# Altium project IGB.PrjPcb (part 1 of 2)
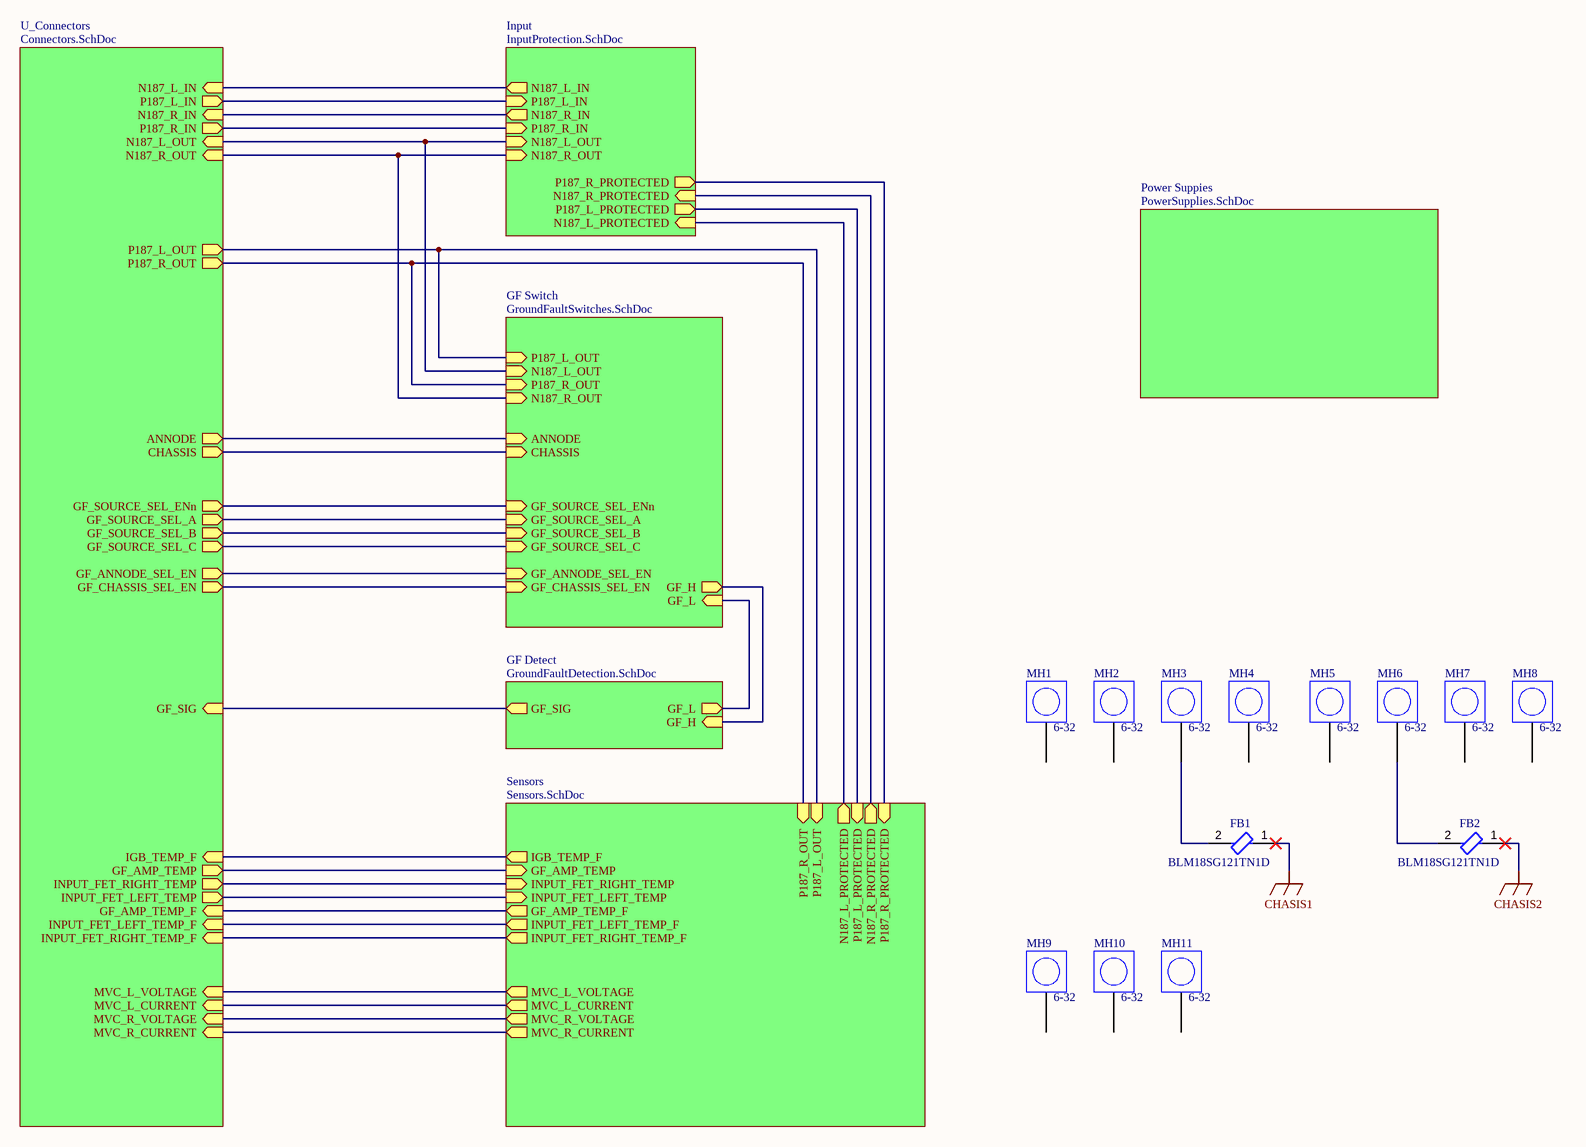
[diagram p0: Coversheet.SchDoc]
Gbl_Cage: 98514; Gbl_CheckedBy: B. SALMI; Gbl_DOC_NO_ASSY_DWG: 91263; Gbl_DOC_NO_BOM: 91261; Gbl_DOC_NO_FAB_DWG: 91262; Gbl_DOC_NO_SCH_DWG: 91255; Gbl_DrawnBy: K.ZACK; Gbl_DSN_APP_DATE: 8/21/2023; Gbl_ENG_APP_DATE: 8/21/2023; Gbl_Engineer: K. ZACK; Gbl_PCB_DWG_NO: 91256; Gbl_Project: MARS2 LVPS; Gbl_Revision: A
7 sheets, 229 parts. Net scope: hierarchical (ports join the sheet entries above them; power ports are global).
Board file: IGB.PcbDoc
Sheets:
  Coversheet.SchDoc
    U_Connectors = Connectors.SchDoc
    GF Detect = GroundFaultDetection.SchDoc
    GF Switch = GroundFaultSwitches.SchDoc
    Input = InputProtection.SchDoc
    Sensors = Sensors.SchDoc
    Power Suppies = PowerSupplies.SchDoc

## Sheet Coversheet.SchDoc: MARS2 LVPS - IGB - Main
size 431 x 279 mm; Organization: ORGANIZATION; Address1: APPLIED PHYSICS LAB; Address2: UNIVERSITY OF WASHINGTON; Address3: 1013 NE 40TH STREET; Address4: SEATTLE, WA 98105; DocumentNumber: 1; Revision: -; SheetNumber: 1; SheetTotal: 7; ENG_APP_DATE: --/--/--; DSN_APP_DATE: --/--/--; CHK_APP_DATE: --/--/--

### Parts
FB1  BLM18SG121TN1D  [FP-BLM18-0_15-t0_5-d1_2-IPC_B]
FB2  BLM18SG121TN1D  [FP-BLM18-0_15-t0_5-d1_2-IPC_B]
MH1  Fastener Size: 6-32  [MH-M3-Footprint-1 - Oversized MARS2]  (hidden comment: MH-MARS2-6-32)  (no BOM)
MH2  Fastener Size: 6-32  [MH-M3-Footprint-1 - Oversized MARS2]  (hidden comment: MH-MARS2-6-32)  (no BOM)
MH3  Fastener Size: 6-32  [MH-M3-Footprint-1 - Oversized MARS2]  (hidden comment: MH-MARS2-6-32)  (no BOM)
MH4  Fastener Size: 6-32  [MH-M3-Footprint-1 - Oversized MARS2]  (hidden comment: MH-MARS2-6-32)  (no BOM)
MH5  Fastener Size: 6-32  [MH-M3-Footprint-1 - Oversized MARS2]  (hidden comment: MH-MARS2-6-32)  (no BOM)
MH6  Fastener Size: 6-32  [MH-M3-Footprint-1 - Oversized MARS2]  (hidden comment: MH-MARS2-6-32)  (no BOM)
MH7  Fastener Size: 6-32  [MH-M3-Footprint-1 - Oversized MARS2]  (hidden comment: MH-MARS2-6-32)  (no BOM)
MH8  Fastener Size: 6-32  [MH-M3-Footprint-1 - Oversized MARS2]  (hidden comment: MH-MARS2-6-32)  (no BOM)
MH9  Fastener Size: 6-32  [MH-M3-Footprint-1 - Oversized MARS2]  (hidden comment: MH-MARS2-6-32)  (no BOM)
MH10  Fastener Size: 6-32  [MH-M3-Footprint-1 - Oversized MARS2]  (hidden comment: MH-MARS2-6-32)  (no BOM)
MH11  Fastener Size: 6-32  [MH-M3-Footprint-1 - Oversized MARS2]  (hidden comment: MH-MARS2-6-32)  (no BOM)

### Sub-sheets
GF Detect = GroundFaultDetection.SchDoc: GF_H (in), GF_SIG (out), GF_L (out)
GF Switch = GroundFaultSwitches.SchDoc: GF_SOURCE_SEL_A (in), GF_SOURCE_SEL_B (in), GF_SOURCE_SEL_ENn (in), N187_R_OUT (in), P187_R_OUT (in), GF_CHASSIS_SEL_EN (in), GF_H (out), P187_L_OUT (in), GF_SOURCE_SEL_C (in), GF_ANNODE_SEL_EN (in), GF_L (in), N187_L_OUT (in), ANNODE (in), CHASSIS (in)
Input = InputProtection.SchDoc: P187_L_IN (in), P187_R_IN (in), P187_R_PROTECTED (out), P187_L_PROTECTED (out), N187_R_IN (out), N187_R_OUT (in), N187_L_IN (out), N187_L_OUT (in), N187_R_PROTECTED (in), N187_L_PROTECTED (in)
Power Suppies = PowerSupplies.SchDoc: no entries
Sensors = Sensors.SchDoc: IGB_TEMP_F (out), GF_AMP_TEMP (in), INPUT_FET_RIGHT_TEMP (in), INPUT_FET_LEFT_TEMP (in), GF_AMP_TEMP_F (out), INPUT_FET_LEFT_TEMP_F (out), INPUT_FET_RIGHT_TEMP_F (out), P187_R_PROTECTED (in), P187_L_PROTECTED (in), MVC_L_CURRENT (out), MVC_L_VOLTAGE (out), MVC_R_CURRENT (out), MVC_R_VOLTAGE (out), N187_R_PROTECTED (out), N187_L_PROTECTED (out), P187_R_OUT (in), P187_L_OUT (in)
U_Connectors = Connectors.SchDoc: P187_R_IN (out), P187_L_IN (out), ANNODE (out), GF_SOURCE_SEL_ENn (out), GF_SIG (in), GF_SOURCE_SEL_A (out), GF_CHASSIS_SEL_EN (out), GF_ANNODE_SEL_EN (out), GF_SOURCE_SEL_C (out), GF_SOURCE_SEL_B (out), INPUT_FET_LEFT_TEMP_F (in), IGB_TEMP_F (in), GF_AMP_TEMP (out), INPUT_FET_RIGHT_TEMP (out), INPUT_FET_RIGHT_TEMP_F (in), INPUT_FET_LEFT_TEMP (out), GF_AMP_TEMP_F (in), CHASSIS (out), MVC_R_CURRENT (in), MVC_L_CURRENT (in), MVC_R_VOLTAGE (in), MVC_L_VOLTAGE (in), N187_R_IN (in), N187_L_IN (in), P187_R_OUT (out), N187_R_OUT (in), P187_L_OUT (out), N187_L_OUT (in)

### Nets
CHASIS1: FB1.1
CHASIS2: FB2.1
GF_SOURCE_SEL_ENn: sheet U_Connectors/GF_SOURCE_SEL_ENn, sheet GF Switch/GF_SOURCE_SEL_ENn
L_INPUT_COMMON: sheet Input/N187_L_PROTECTED, sheet Sensors/N187_L_PROTECTED
N187_L_OUT: sheet U_Connectors/N187_L_IN, sheet U_Connectors/N187_L_OUT, sheet GF Switch/N187_L_OUT, sheet Input/N187_L_IN, sheet Input/N187_L_OUT
N187_R_OUT: sheet U_Connectors/N187_R_IN, sheet U_Connectors/N187_R_OUT, sheet GF Switch/N187_R_OUT, sheet Input/N187_R_IN, sheet Input/N187_R_OUT
P187_L_OUT: sheet U_Connectors/P187_L_OUT, sheet GF Switch/P187_L_OUT, sheet Sensors/P187_L_OUT
P187_R_OUT: sheet U_Connectors/P187_R_OUT, sheet GF Switch/P187_R_OUT, sheet Sensors/P187_R_OUT
R_INPUT_COMMON: sheet Input/N187_R_PROTECTED, sheet Sensors/N187_R_PROTECTED
NetC21_2: sheet U_Connectors/MVC_R_CURRENT, sheet Sensors/MVC_R_CURRENT
NetC22_2: sheet U_Connectors/GF_AMP_TEMP_F, sheet Sensors/GF_AMP_TEMP_F
NetC23_2: sheet U_Connectors/INPUT_FET_LEFT_TEMP_F, sheet Sensors/INPUT_FET_LEFT_TEMP_F
NetC24_2: sheet U_Connectors/INPUT_FET_RIGHT_TEMP_F, sheet Sensors/INPUT_FET_RIGHT_TEMP_F
NetC25_2: sheet U_Connectors/MVC_R_VOLTAGE, sheet Sensors/MVC_R_VOLTAGE
NetC26_2: sheet U_Connectors/IGB_TEMP_F, sheet Sensors/IGB_TEMP_F
NetC29_2: sheet U_Connectors/MVC_L_CURRENT, sheet Sensors/MVC_L_CURRENT
NetC30_2: sheet U_Connectors/MVC_L_VOLTAGE, sheet Sensors/MVC_L_VOLTAGE
NetFB1_2: FB1.2 MH3.1
NetFB2_2: FB2.2 MH6.1
NetJ1_A: sheet U_Connectors/P187_R_IN, sheet Input/P187_R_IN
NetJ2_A: sheet U_Connectors/P187_L_IN, sheet Input/P187_L_IN
NetJ3_1: sheet U_Connectors/ANNODE, sheet GF Switch/ANNODE
NetJ3_2: sheet U_Connectors/CHASSIS, sheet GF Switch/CHASSIS
NetJ9_1: sheet U_Connectors/GF_SOURCE_SEL_A, sheet GF Switch/GF_SOURCE_SEL_A
NetJ9_3: sheet U_Connectors/GF_SOURCE_SEL_B, sheet GF Switch/GF_SOURCE_SEL_B
NetJ9_5: sheet U_Connectors/GF_SOURCE_SEL_C, sheet GF Switch/GF_SOURCE_SEL_C
NetJ9_9: sheet U_Connectors/GF_ANNODE_SEL_EN, sheet GF Switch/GF_ANNODE_SEL_EN
NetJ9_11: sheet U_Connectors/GF_CHASSIS_SEL_EN, sheet GF Switch/GF_CHASSIS_SEL_EN
NetJ9_47: sheet U_Connectors/GF_SIG, sheet GF Detect/GF_SIG
NetJ10_1: sheet U_Connectors/GF_AMP_TEMP, sheet Sensors/GF_AMP_TEMP
NetJ10_2: sheet U_Connectors/INPUT_FET_RIGHT_TEMP, sheet Sensors/INPUT_FET_RIGHT_TEMP
NetJ10_3: sheet U_Connectors/INPUT_FET_LEFT_TEMP, sheet Sensors/INPUT_FET_LEFT_TEMP
NetJ17_1: sheet Input/P187_R_PROTECTED, sheet Sensors/P187_R_PROTECTED
NetJ20_1: sheet Input/P187_L_PROTECTED, sheet Sensors/P187_L_PROTECTED
NetJ21_1: sheet GF Detect/GF_H, sheet GF Switch/GF_H
NetJ22_1: sheet GF Detect/GF_L, sheet GF Switch/GF_L

Not connected (* = marked no-connect by the designer): MH1 1; MH2 1; MH4 1; MH5 1; MH7 1; MH8 1; MH9 1; MH10 1; MH11 1

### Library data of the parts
FB1 FB2 = CMP-00000-1: Ferrite Beads Multi-Layer 120Ohm 25% 100MHz 3A 0.025Ohm DCR 0603 T/R; DC Resistance (DCR): 25mR; Number of Circuits: 1; Shielding: Unshielded; Material: Steel,Ferrite; Impedance: 120R
MH1-MH11 = CMP-00028-00015-1: MARS2 Project 6-32 Mounting Hole Plated .; Plated: Yes

## Sheet Connectors.SchDoc: MARS2 LVPS - IGB - Connectors
size 431 x 279 mm; Organization: ORGANIZATION; Address1: APPLIED PHYSICS LAB; Address2: UNIVERSITY OF WASHINGTON; Address3: 1013 NE 40TH STREET; Address4: SEATTLE, WA 98105; DocumentNumber: 2; Revision: -; SheetNumber: 2; SheetTotal: 7; ENG_APP_DATE: --/--/--; DSN_APP_DATE: --/--/--; CHK_APP_DATE: --/--/--
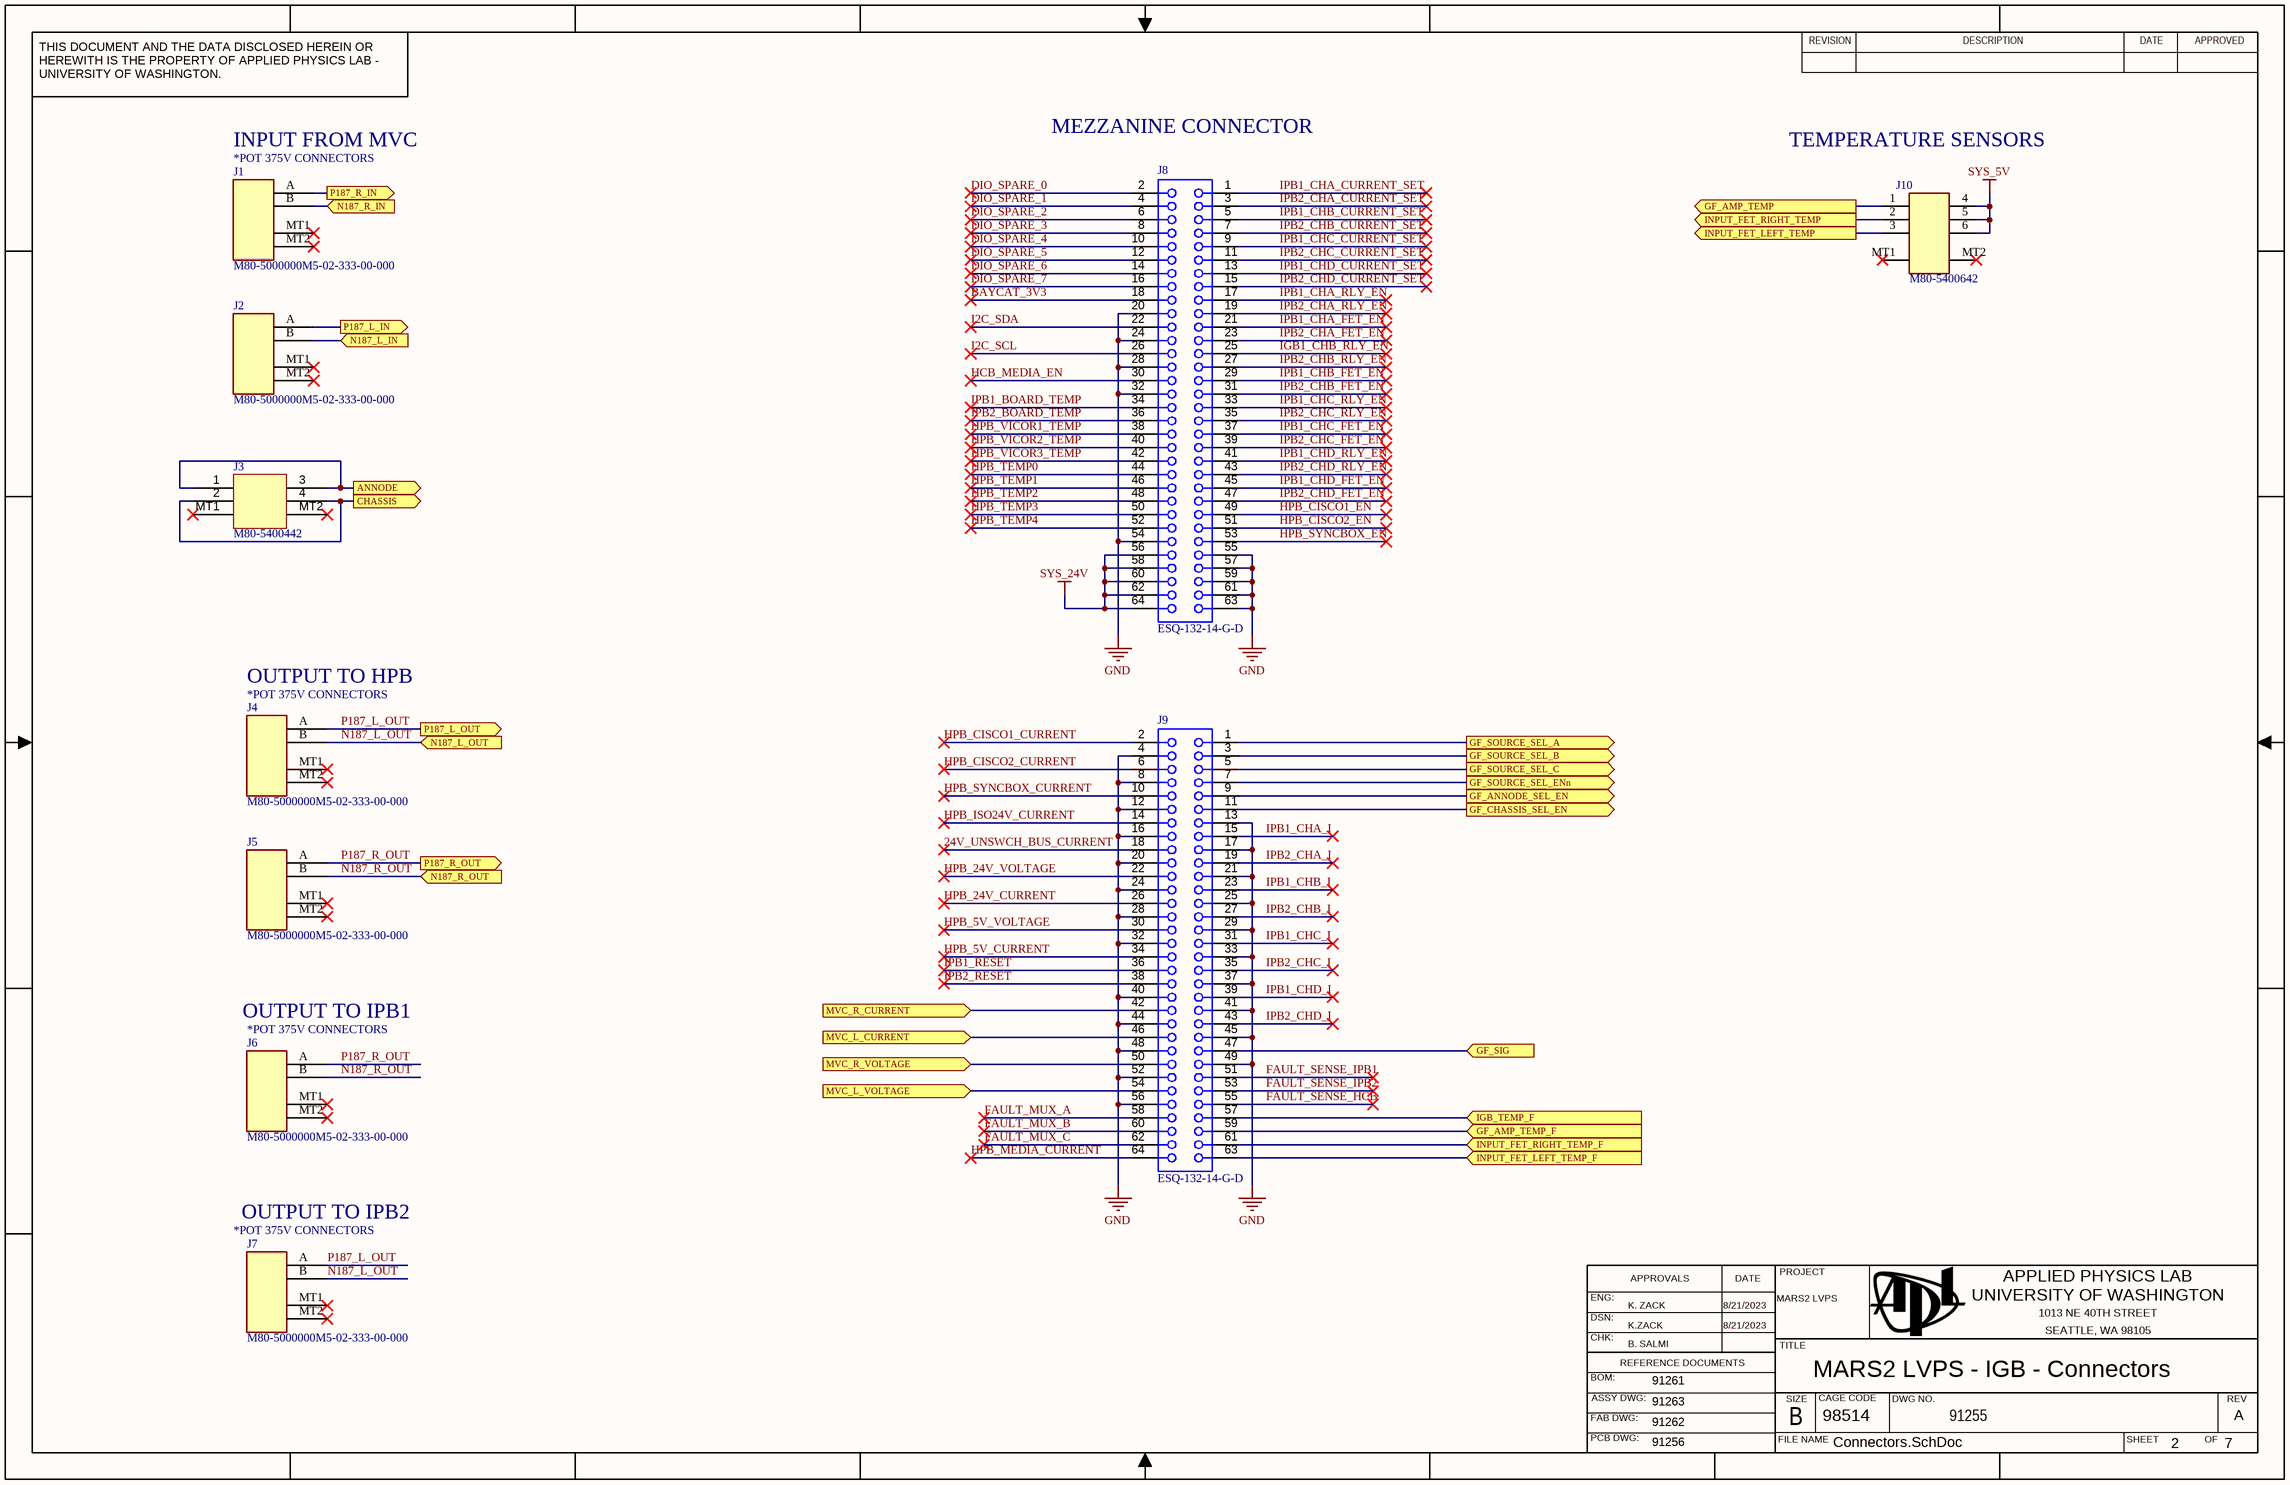
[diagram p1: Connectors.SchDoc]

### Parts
J1  M80-5000000M5-02-333-00-000  [FP-M80-5000000M5-02-333-0-MFG]
J2  M80-5000000M5-02-333-00-000  [FP-M80-5000000M5-02-333-0-MFG]
J3  M80-5400442  [M80-5400442-Footprint-1]
J4  M80-5000000M5-02-333-00-000  [FP-M80-5000000M5-02-333-0-MFG]
J5  M80-5000000M5-02-333-00-000  [FP-M80-5000000M5-02-333-0-MFG]
J6  M80-5000000M5-02-333-00-000  [FP-M80-5000000M5-02-333-0-MFG]
J7  M80-5000000M5-02-333-00-000  [FP-M80-5000000M5-02-333-0-MFG]
J8  ESQ-132-14-G-D  [SMTC-ESQ-132-14-X-D]
J9  ESQ-132-14-G-D  [SMTC-ESQ-132-14-X-D]
J10  M80-5400642  [FP-M80-5400642-MFG]

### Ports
ANNODE (out), CHASSIS (out), GF_AMP_TEMP (out), GF_AMP_TEMP_F (in), GF_ANNODE_SEL_EN (out), GF_CHASSIS_SEL_EN (out), GF_SIG (in), GF_SOURCE_SEL_A (out), GF_SOURCE_SEL_B (out), GF_SOURCE_SEL_C (out), GF_SOURCE_SEL_ENn (out), IGB_TEMP_F (in), INPUT_FET_LEFT_TEMP (out), INPUT_FET_LEFT_TEMP_F (in), INPUT_FET_RIGHT_TEMP (out), INPUT_FET_RIGHT_TEMP_F (in), MVC_L_CURRENT (in), MVC_L_VOLTAGE (in), MVC_R_CURRENT (in), MVC_R_VOLTAGE (in), N187_L_IN (in), N187_L_OUT (in), N187_R_IN (in), N187_R_OUT (in), P187_L_IN (out), P187_L_OUT (out), P187_R_IN (out), P187_R_OUT (out)

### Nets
GND: J8.20 J8.24 J8.28 J8.32 J8.54 J8.55 J8.57 J8.59 J8.61 J8.63 J9.4 J9.8 J9.12 J9.13 J9.16 J9.17 J9.20 J9.21 J9.24 J9.25 J9.28 J9.29 J9.32 J9.33 J9.37 J9.40 J9.41 J9.44 J9.45 J9.48 J9.49 J9.52 J9.56
SYS_5V: J10.4 J10.5 J10.6
SYS_24V: J8.56 J8.58 J8.60 J8.62 J8.64
24V_UNSWCH_BUS_CURRENT: J9.18
BAYCAT_3V3: J8.18
DIO_SPARE_0: J8.2
DIO_SPARE_1: J8.4
DIO_SPARE_2: J8.6
DIO_SPARE_3: J8.8
DIO_SPARE_4: J8.10
DIO_SPARE_5: J8.12
DIO_SPARE_6: J8.14
DIO_SPARE_7: J8.16
FAULT_MUX_A: J9.58
FAULT_MUX_B: J9.60
FAULT_MUX_C: J9.62
FAULT_SENSE_HCB: J9.55
FAULT_SENSE_IPB1: J9.51
FAULT_SENSE_IPB2: J9.53
GF_SOURCE_SEL_ENn: J9.7 ; port GF_SOURCE_SEL_ENn
HCB_MEDIA_EN: J8.30
HPB_5V_CURRENT: J9.34
HPB_5V_VOLTAGE: J9.30
HPB_24V_CURRENT: J9.26
HPB_24V_VOLTAGE: J9.22
HPB_CISCO1_CURRENT: J9.2
HPB_CISCO1_EN: J8.49
HPB_CISCO2_CURRENT: J9.6
HPB_CISCO2_EN: J8.51
HPB_ISO24V_CURRENT: J9.14
HPB_MEDIA_CURRENT: J9.64
HPB_SYNCBOX_CURRENT: J9.10
HPB_SYNCBOX_EN: J8.53
HPB_TEMP0: J8.44
HPB_TEMP1: J8.46
HPB_TEMP2: J8.48
HPB_TEMP3: J8.50
HPB_TEMP4: J8.52
HPB_VICOR1_TEMP: J8.38
HPB_VICOR2_TEMP: J8.40
HPB_VICOR3_TEMP: J8.42
I2C_SCL: J8.26
I2C_SDA: J8.22
IGB1_CHB_RLY_EN: J8.25
IPB1_BOARD_TEMP: J8.34
IPB1_CHA_CURRENT_SET: J8.1
IPB1_CHA_FET_EN: J8.21
IPB1_CHA_I: J9.15
IPB1_CHA_RLY_EN: J8.17
IPB1_CHB_CURRENT_SET: J8.5
IPB1_CHB_FET_EN: J8.29
IPB1_CHB_I: J9.23
IPB1_CHC_CURRENT_SET: J8.9
IPB1_CHC_FET_EN: J8.37
IPB1_CHC_I: J9.31
IPB1_CHC_RLY_EN: J8.33
IPB1_CHD_CURRENT_SET: J8.13
IPB1_CHD_FET_EN: J8.45
IPB1_CHD_I: J9.39
IPB1_CHD_RLY_EN: J8.41
IPB1_RESET: J9.36
IPB2_BOARD_TEMP: J8.36
IPB2_CHA_CURRENT_SET: J8.3
IPB2_CHA_FET_EN: J8.23
IPB2_CHA_I: J9.19
IPB2_CHA_RLY_EN: J8.19
IPB2_CHB_CURRENT_SET: J8.7
IPB2_CHB_FET_EN: J8.31
IPB2_CHB_I: J9.27
IPB2_CHB_RLY_EN: J8.27
IPB2_CHC_CURRENT_SET: J8.11
IPB2_CHC_FET_EN: J8.39
IPB2_CHC_I: J9.35
IPB2_CHC_RLY_EN: J8.35
IPB2_CHD_CURRENT_SET: J8.15
IPB2_CHD_FET_EN: J8.47
IPB2_CHD_I: J9.43
IPB2_CHD_RLY_EN: J8.43
IPB2_RESET: J9.38
N187_L_OUT: J2.B J4.B J7.B ; port N187_L_IN, port N187_L_OUT
N187_R_OUT: J1.B J5.B J6.B ; port N187_R_IN, port N187_R_OUT
P187_L_OUT: J4.A J7.A ; port P187_L_OUT
P187_R_OUT: J5.A J6.A ; port P187_R_OUT
NetC21_2: J9.42 ; port MVC_R_CURRENT
NetC22_2: J9.59 ; port GF_AMP_TEMP_F
NetC23_2: J9.63 ; port INPUT_FET_LEFT_TEMP_F
NetC24_2: J9.61 ; port INPUT_FET_RIGHT_TEMP_F
NetC25_2: J9.50 ; port MVC_R_VOLTAGE
NetC26_2: J9.57 ; port IGB_TEMP_F
NetC29_2: J9.46 ; port MVC_L_CURRENT
NetC30_2: J9.54 ; port MVC_L_VOLTAGE
NetJ1_A: J1.A ; port P187_R_IN
NetJ2_A: J2.A ; port P187_L_IN
NetJ3_1: J3.1 J3.3 ; port ANNODE
NetJ3_2: J3.2 J3.4 ; port CHASSIS
NetJ9_1: J9.1 ; port GF_SOURCE_SEL_A
NetJ9_3: J9.3 ; port GF_SOURCE_SEL_B
NetJ9_5: J9.5 ; port GF_SOURCE_SEL_C
NetJ9_9: J9.9 ; port GF_ANNODE_SEL_EN
NetJ9_11: J9.11 ; port GF_CHASSIS_SEL_EN
NetJ9_47: J9.47 ; port GF_SIG
NetJ10_1: J10.1 ; port GF_AMP_TEMP
NetJ10_2: J10.2 ; port INPUT_FET_RIGHT_TEMP
NetJ10_3: J10.3 ; port INPUT_FET_LEFT_TEMP

Not connected (* = marked no-connect by the designer): J1 MT1(MNT_1)* MT2(MNT_2)*; J2 MT1(MNT_1)* MT2(MNT_2)*; J3 MT1* MT2*; J4 MT1(MNT_1)* MT2(MNT_2)*; J5 MT1(MNT_1)* MT2(MNT_2)*; J6 MT1(MNT_1)* MT2(MNT_2)*; J7 MT1(MNT_1)* MT2(MNT_2)*; J10 MT1* MT2*

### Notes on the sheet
- (near J1) INPUT FROM MVC
- (near J1) *POT 375V CONNECTORS
- MEZZANINE CONNECTOR
- TEMPERATURE SENSORS
- (near J4) OUTPUT TO HPB
- (near J4) *POT 375V CONNECTORS
- (near J6) OUTPUT TO IPB1
- (near J6) *POT 375V CONNECTORS
- (near J7) *POT 375V CONNECTORS
- (near J7) OUTPUT TO IPB2

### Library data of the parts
J1 J2 J4-J7 = CMP-002-00075-3: Conn Header R/a 2POS 4MM; Manufacturer: Harwin; Number of Positions: 2; Pitch: 4.00mm; Current Rating: 40A; Contact Resistance: 25mR; Voltage Rating: 800V; Gender: Male; Insulation Resistance: 100MR
J3 = CMP-002-00095-3: HARWIN - M80-5400442 - Wire-To-Board Connector, 2 mm, 4 Contacts, Header, Datamate J-Tek M80 Series, Through Hole, 2 Rows; Number of Positions: 4; Maximum Voltage: 800V; Gender: Male; Pitch: 2mm; Current Rating: 2.2A; Contact Resistance: 25mR; Insulation Resistance: 100MR
J8 J9 = CMP-002-00093-2: Conn Elevated Socket SKT 64 POS 2.54mm Solder ST Top Entry Thru-Hole Tube; Voltage Rating (AC): 550V; Current Rating: 6.9A; Number of Contacts: 64; Row Spacing: 0.1inch; Connector Type: Receptacle; Contact Resistance: 10mR
J10 = CMP-002-00076-5: Conn Header R/a 6POS 2MM; Manufacturer: Harwin; Current Rating: 3A; Contact Resistance: 25mR; Gender: Male; Max Voltage Rating (AC): 120V; Voltage Rating: 800V; Number of Contacts: 6; Insulation Resistance: 100MR

## Sheet GroundFaultDetection.SchDoc: MARS2 LVPS - IGB - GND Fault Detect
size 431 x 279 mm; Organization: ORGANIZATION; Address1: APPLIED PHYSICS LAB; Address2: UNIVERSITY OF WASHINGTON; Address3: 1013 NE 40TH STREET; Address4: SEATTLE, WA 98105; DocumentNumber: 5; Revision: -; SheetNumber: 5; SheetTotal: 7; ENG_APP_DATE: --/--/--; DSN_APP_DATE: --/--/--; CHK_APP_DATE: --/--/--
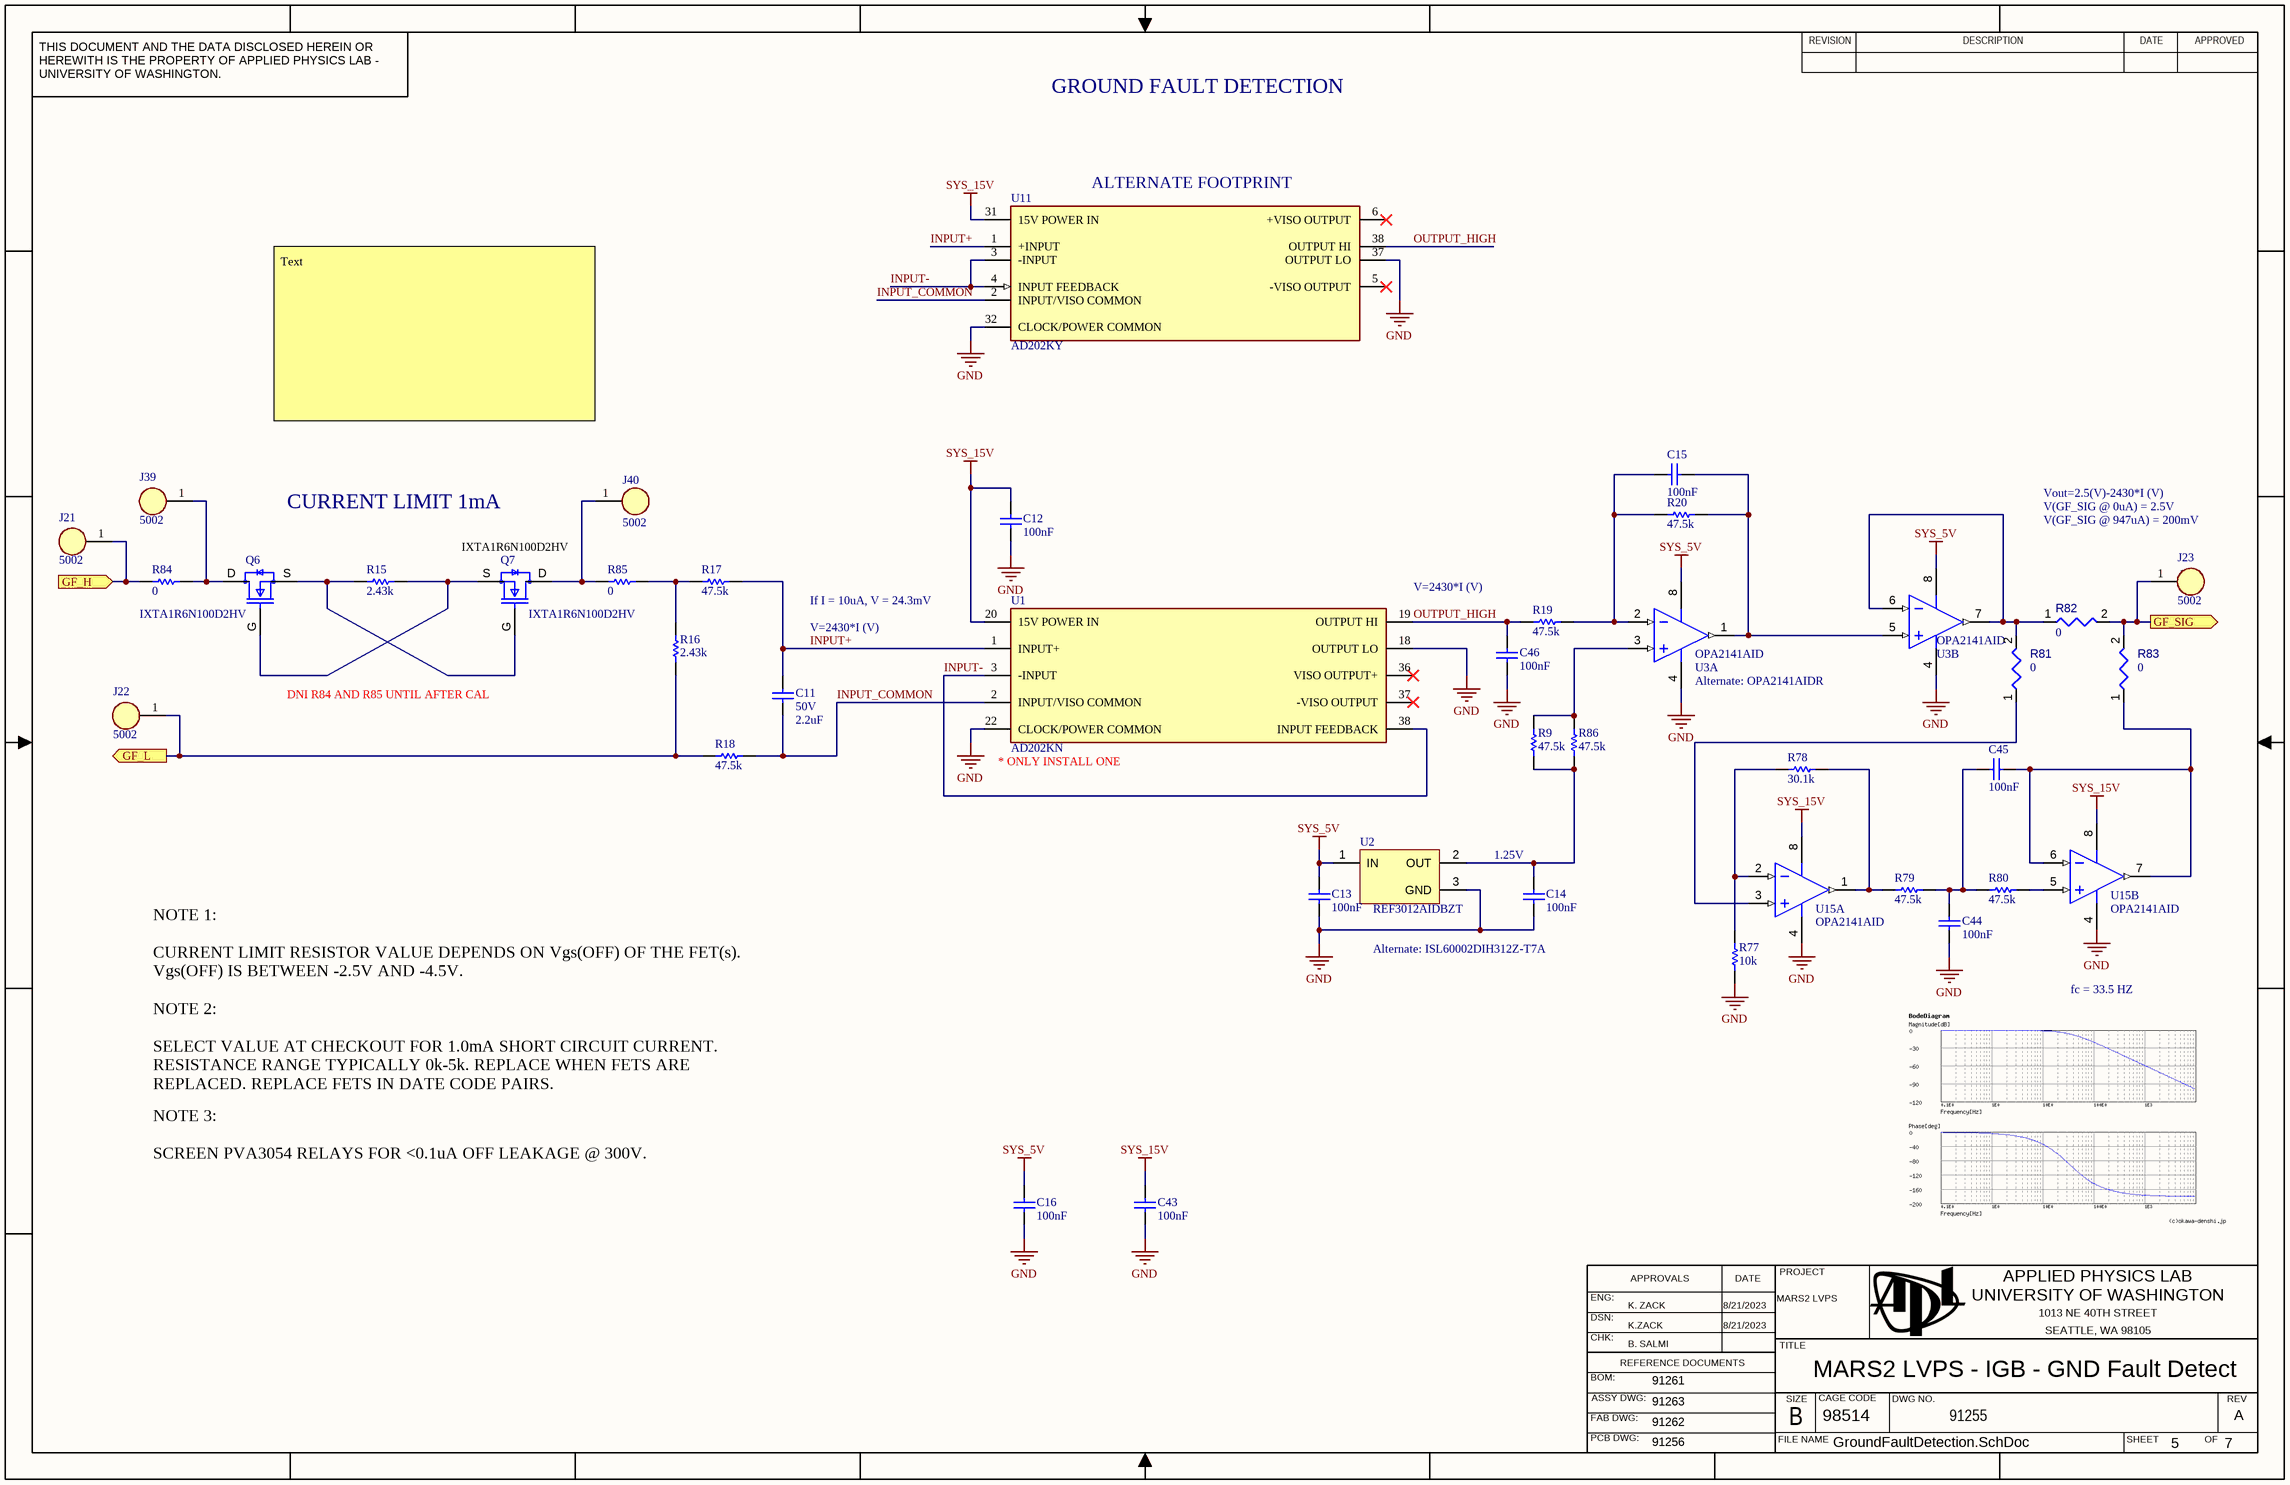
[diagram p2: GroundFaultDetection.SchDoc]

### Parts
C11  Voltage Rating: 50V  Capacitance: 2.2uF  [CAPC3225X270X30ML30]  (hidden comment: Capacitor 2.2uF 10%, 50V, X7R, 1210)
C12  value 100nF  [CAPC1608X90X40NL10T20]  (hidden comment: Capacitor 100 nF +/-10% 50 V 0603)
C13  value 100nF  [CAPC1608X90X40NL10T20]  (hidden comment: Capacitor 100 nF +/-10% 50 V 0603)
C14  value 100nF  [CAPC1608X90X40NL10T20]  (hidden comment: Capacitor 100 nF +/-10% 50 V 0603)
C15  value 100nF  [CAPC1608X90X40NL10T20]  (hidden comment: Capacitor 100 nF +/-10% 50 V 0603)
C16  value 100nF  [CAPC1608X90X40NL10T20]  (hidden comment: Capacitor 100 nF +/-10% 50 V 0603)
C43  value 100nF  [CAPC1608X90X40NL10T20]  (hidden comment: Capacitor 100 nF +/-10% 50 V 0603)
C44  value 100nF  [CAPC1608X90X40NL10T20]  (hidden comment: Capacitor 100 nF +/-10% 50 V 0603)
C45  value 100nF  [CAPC1608X90X40NL10T20]  (hidden comment: Capacitor 100 nF +/-10% 50 V 0603)
C46  value 100nF  [CAPC1608X90X40NL10T20]  (hidden comment: Capacitor 100 nF +/-10% 50 V 0603)
J21  5002  [FP-5002-MFG]
J22  5002  [FP-5002-MFG]
J23  5002  [FP-5002-MFG]
J39  5002  [FP-5002-MFG]
J40  5002  [FP-5002-MFG]
Q6  IXTA1R6N100D2HV  [IXTA1R6N100D2HV-Footprint-1]
Q7  IXTA1R6N100D2HV  [IXTA1R6N100D2HV-Footprint-1]
R9  value 47.5k  [RESC1608X55X25ML10T15]  (hidden comment: Resistor 47K5 +/-1% 0603 100 mW)
R15  value 2.43k  [RESC1608X55X25ML10T15]  (hidden comment: Resistor 2K43+/-1% 0603 100 mW)
R16  value 2.43k  [RESC1608X55X25ML10T15]  (hidden comment: Resistor 2K43+/-1% 0603 100 mW)
R17  value 47.5k  [RESC1608X55X25ML10T15]  (hidden comment: Resistor 47K5 +/-1% 0603 100 mW)
R18  value 47.5k  [RESC1608X55X25ML10T15]  (hidden comment: Resistor 47K5 +/-1% 0603 100 mW)
R19  value 47.5k  [RESC1608X55X25ML10T15]  (hidden comment: Resistor 47K5 +/-1% 0603 100 mW)
R20  value 47.5k  [RESC1608X55X25ML10T15]  (hidden comment: Resistor 47K5 +/-1% 0603 100 mW)
R77  value 10k  [RESC1608X55X25ML10T15]  (hidden comment: Resistor 10k +/-1% 0603 100 mW)
R78  value 30.1k  [RESC1608X55X25ML10T15]  (hidden comment: Resistor 30K1 +/-1% 0603 100 mW)
R79  value 47.5k  [RESC1608X55X25ML10T15]  (hidden comment: Resistor 47K5 +/-1% 0603 100 mW)
R80  value 47.5k  [RESC1608X55X25ML10T15]  (hidden comment: Resistor 47K5 +/-1% 0603 100 mW)
R81  value 0  [RESC0603(1608)_L]  (hidden comment: Jumper 0603)
R82  value 0  [RESC0603(1608)_L]  (hidden comment: Jumper 0603)
R83  value 0  [RESC0603(1608)_L]  (hidden comment: Jumper 0603)
R84  value 0  [RESC1608X55X25ML10T15]  (hidden comment: Resistor 0R +/- 5% 0603 100 mW)
R85  value 0  [RESC1608X55X25ML10T15]  (hidden comment: Resistor 0R +/- 5% 0603 100 mW)
R86  value 47.5k  [RESC1608X55X25ML10T15]  (hidden comment: Resistor 47K5 +/-1% 0603 100 mW)
U1  AD202KN  [FP-AD202KN-MFG]
U2  REF3012AIDBZT  [DBZ0003A_N]
U3  OPA2141AID  [D0008A_L]  (parts A,B of 2)
U11  AD202KY  [FP-Y-10-MFG]
U15  OPA2141AID  [D0008A_L]  (parts A,B of 2)

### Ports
GF_H (in), GF_L (out), GF_SIG (out)

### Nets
GND: C12.1 C13.1 C14.1 C16.1 C43.1 C44.1 C46.1 R77.1 U1.18(OUTPUT_LO) U1.22(CLOCK/POWER_COMMON) U2.3(GND) U3.4(V-) U11.32(CLOCK/POWER_COMMON) U11.37(OUTPUT_LO) U15.4(V-)
SYS_5V: C13.2 C16.2 U2.1(IN) U3.8(V+)
SYS_15V: C12.2 C43.2 U1.20(15V_POWER_IN) U11.31(15V_POWER_IN) U15.8(V+)
INPUT+: C11.2 R17.2 U1.1(INPUT+) U11.1(+INPUT)
INPUT-: U1.3(-INPUT) U1.38(INPUT_FEEDBACK) U11.3(-INPUT) U11.4(INPUT_FEEDBACK)
INPUT_COMMON: C11.1 R18.2 U1.2(INPUT/VISO_COMMON) U11.2(INPUT/VISO_COMMON)
OUTPUT_HIGH: C46.2 R19.1 U1.19(OUTPUT_HI) U11.38(OUTPUT_HI)
NetC14_2: C14.2 R9.1 R86.1 U2.2(OUT)
NetC15_1: C15.1 R19.2 R20.1 U3.2(IN_A-)
NetC15_2: C15.2 R20.2 U3.1(OUT_A) U3.5(IN_B+)
NetC44_2: C44.2 C45.1 R79.2 R80.1
NetC45_2: C45.2 R83.1 U15.6(IN_B-) U15.7(OUT_B)
NetJ9_47: J23.1 R82.2 R83.2 ; port GF_SIG
NetJ21_1: J21.1 R84.1 ; port GF_H
NetJ22_1: J22.1 R16.1 R18.1 ; port GF_L
NetJ39_1: J39.1 Q6.D(DRAIN) R84.2
NetJ40_1: J40.1 Q7.D(DRAIN) R85.1
NetQ6_G: Q6.G(GATE) Q7.S(SOURCE) R15.2
NetQ6_S: Q6.S(SOURCE) Q7.G(GATE) R15.1
NetR9_2: R9.2 R86.2 U3.3(IN_A+)
NetR16_2: R16.2 R17.1 R85.2
NetR77_2: R77.2 R78.1 U15.2(IN_A-)
NetR78_2: R78.2 R79.1 U15.1(OUT_A)
NetR80_2: R80.2 U15.5(IN_B+)
NetR81_1: R81.1 U15.3(IN_A+)
NetR81_2: R81.2 R82.1 U3.6(IN_B-) U3.7(OUT_B)

Not connected (* = marked no-connect by the designer): U1 36(VISO_OUTPUT+)* 37(-VISO_OUTPUT)*; U11 5(-VISO_OUTPUT)* 6(+VISO_OUTPUT)*

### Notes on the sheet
- GROUND FAULT DETECTION
- (near U11) ALTERNATE FOOTPRINT
- Text
- Vout=2.5(V)-2430*I (V)
- CURRENT LIMIT 1mA
- IXTA1R6N100D2HV
- V(GF_SIG @ 947uA) = 200mV
- V(GF_SIG @ 0uA) = 2.5V
- V=2430*I (V)
- If I = 10uA, V = 24.3mV
- DNI R84 AND R85 UNTIL AFTER CAL
- (near U3) Alternate: OPA2141AIDR
- (near U1) * ONLY INSTALL ONE
- (near C14) 1.25V
- Alternate: ISL60002DIH312Z-T7A
- NOTE 1:
  CURRENT LIMIT RESISTOR VALUE DEPENDS ON Vgs(OFF) OF THE FET(s). Vgs(OFF) IS BETWEEN -2.5V AND -4.5V.
- fc = 33.5 HZ
- NOTE 2:
  SELECT VALUE AT CHECKOUT FOR 1.0mA SHORT CIRCUIT CURRENT. RESISTANCE RANGE TYPICALLY 0k-5k. REPLACE WHEN FETS ARE REPLACED. REPLACE FETS IN DATE CODE PAIRS.
- NOTE 3:
  SCREEN PVA3054 RELAYS FOR <0.1uA OFF LEAKAGE @ 300V.

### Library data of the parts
C11 = CMP-001-00182-8: Chip Capacitor, 2.2uF, 10%, 50 V, X7R 1210 (3225 Metric); Decade: 1uF; Capacitor Type: Ceramic
C12-C16 C43-C46 = CMP-001-00017-14: Chip Capacitor, 100 nF, +/- 10%, 50 V, 0603 (1608 Metric); Voltage Rating: 50V; Capacitor Type: Ceramic
J21-J23 J39 J40 = CMP-002-00083-3: TEST POINT PC MINI .040D WHITE; Body Material: Bronze
Q6 Q7 = CMP-013-00046-3: Mosfet N-ch 1000V 1.6A TO263HV; Rds On Max: 10R; Max Power Dissipation: 100W; Input Capacitance: 645pF; Drain to Source Voltage (Vdss): 1kV; Transistor Type: NMOS
R9 R17-R20 R79 R80 R86 = CMP-009-00999-3: Chip Resistor, 47.5k Ohm, +/- 1%, 0.1 W, -55 to 155 degC, 0603 (1608 Metric); Voltage Rating: 75V; Power: 100mW; Decade: 10k
R15 R16 = CMP-009-00594-2: Chip Resistor, 2.43 KOhm, +/- 1%, 0.1 W, -55 to 155 degC, 0603 (1608 Metric); Power: 100mW; Decade: 1k; Voltage Rating: 75V
R77 = CMP-009-00017-7: Chip Resistor, 10 KOhm, +/- 1%, 01 W, -55 to 155 degC, 0603 (1608 Metric); Voltage Rating: 50V; Power: 100mW
R78 = CMP-009-00980-3: Chip Resistor, 30.1k Ohm, +/- 1%, 0.1 W, -55 to 155 degC, 0603 (1608 Metric); Decade: 10k; Power: 100mW; Voltage Rating: 75V
R81-R83 = CMP-009-00175-3
R84 R85 = CMP-009-00006-6: Chip Resistor, 0 Ohm, 0.1 W, -55 to 155 degC, 0603 (1608 Metric); Voltage Rating: 50V; Power: 100mW
U1 = CMP-014-00004-2: SP Amp Isolated Amp Single 16.5 Volt 11-Pin PDIP; Operating Supply Voltage: 15V; Operating Supply Current: 5mA; Supply Current: 35mA; Input Offset Voltage (Vos): 5mV; Number of Amplifiers: 1; Max Supply Voltage: 16.5V; Amplifier Type: ISOLATION; Bandwidth: 5kHz; Gain Bandwidth Product: 2kHz; Number of Circuits: 2; Input Resistance: 2GR; Output Current per Channel: 400uA; Isolation Voltage: 1.5kV; Common Mode Rejection Ratio: 130dB; Min Supply Voltage: 13.5V; Input Bias Current: 30pA; Voltage Gain: 40dB
U2 = CMP-019-00057-2: 1.25V 50ppm/Degrees C, 50uA in SOT23-3 Series (Bandgap) Voltage Reference 3-SOT-23 -40 to 125; Max Input Voltage: 5.5V; Temperature Coefficient: 50ppm/°C; Supply Current: 42uA; Reference Type: Series,Fixed; Min Output Voltage: 1.248V; Number of Channels: 1; Min Input Voltage: 1.8V; Output Current: 25mA; Tolerance: 0.2%
U3 U15 = CMP-014-00005-2: Dual, 10MHz, Single Supply, Low Noise, JFET Precision Amplifier 8-SOIC -40 to 125; Max Frequency: 1MHz; Slew Rate: 20V/µs; Input Offset Voltage (Vos): 1mV; Number of Circuits: 2; Operating Supply Current: 1.8mA; Power Supply Rejection Ratio (PSRR): 137.07dB; Voltage Gain: 126dB; Operating Supply Voltage: 18V; Supply Current: 2.3mA; Max I/O Voltage: 3.5mV; Min Supply Voltage: 4.5V; Input Bias Current: 20pA; Output Current: 36mA; Min Dual Supply Voltage: 2.25V; Max Supply Voltage: 36V; Common Mode Rejection Ratio: 120dB
U11 = CMP-014-00002-1: Amplifier; Isolation Amplifier; 15 V + 10%; 2 kHz; + 5 V; 130 dB; SIP; -40 degC

## Sheet GroundFaultSwitches.SchDoc: MARS2 LVPS - IGB - GND Fault SW
size 431 x 279 mm; Organization: ORGANIZATION; Address1: APPLIED PHYSICS LAB; Address2: UNIVERSITY OF WASHINGTON; Address3: 1013 NE 40TH STREET; Address4: SEATTLE, WA 98105; DocumentNumber: 6; Revision: -; SheetNumber: 6; SheetTotal: 7; ENG_APP_DATE: --/--/--; DSN_APP_DATE: --/--/--; CHK_APP_DATE: --/--/--
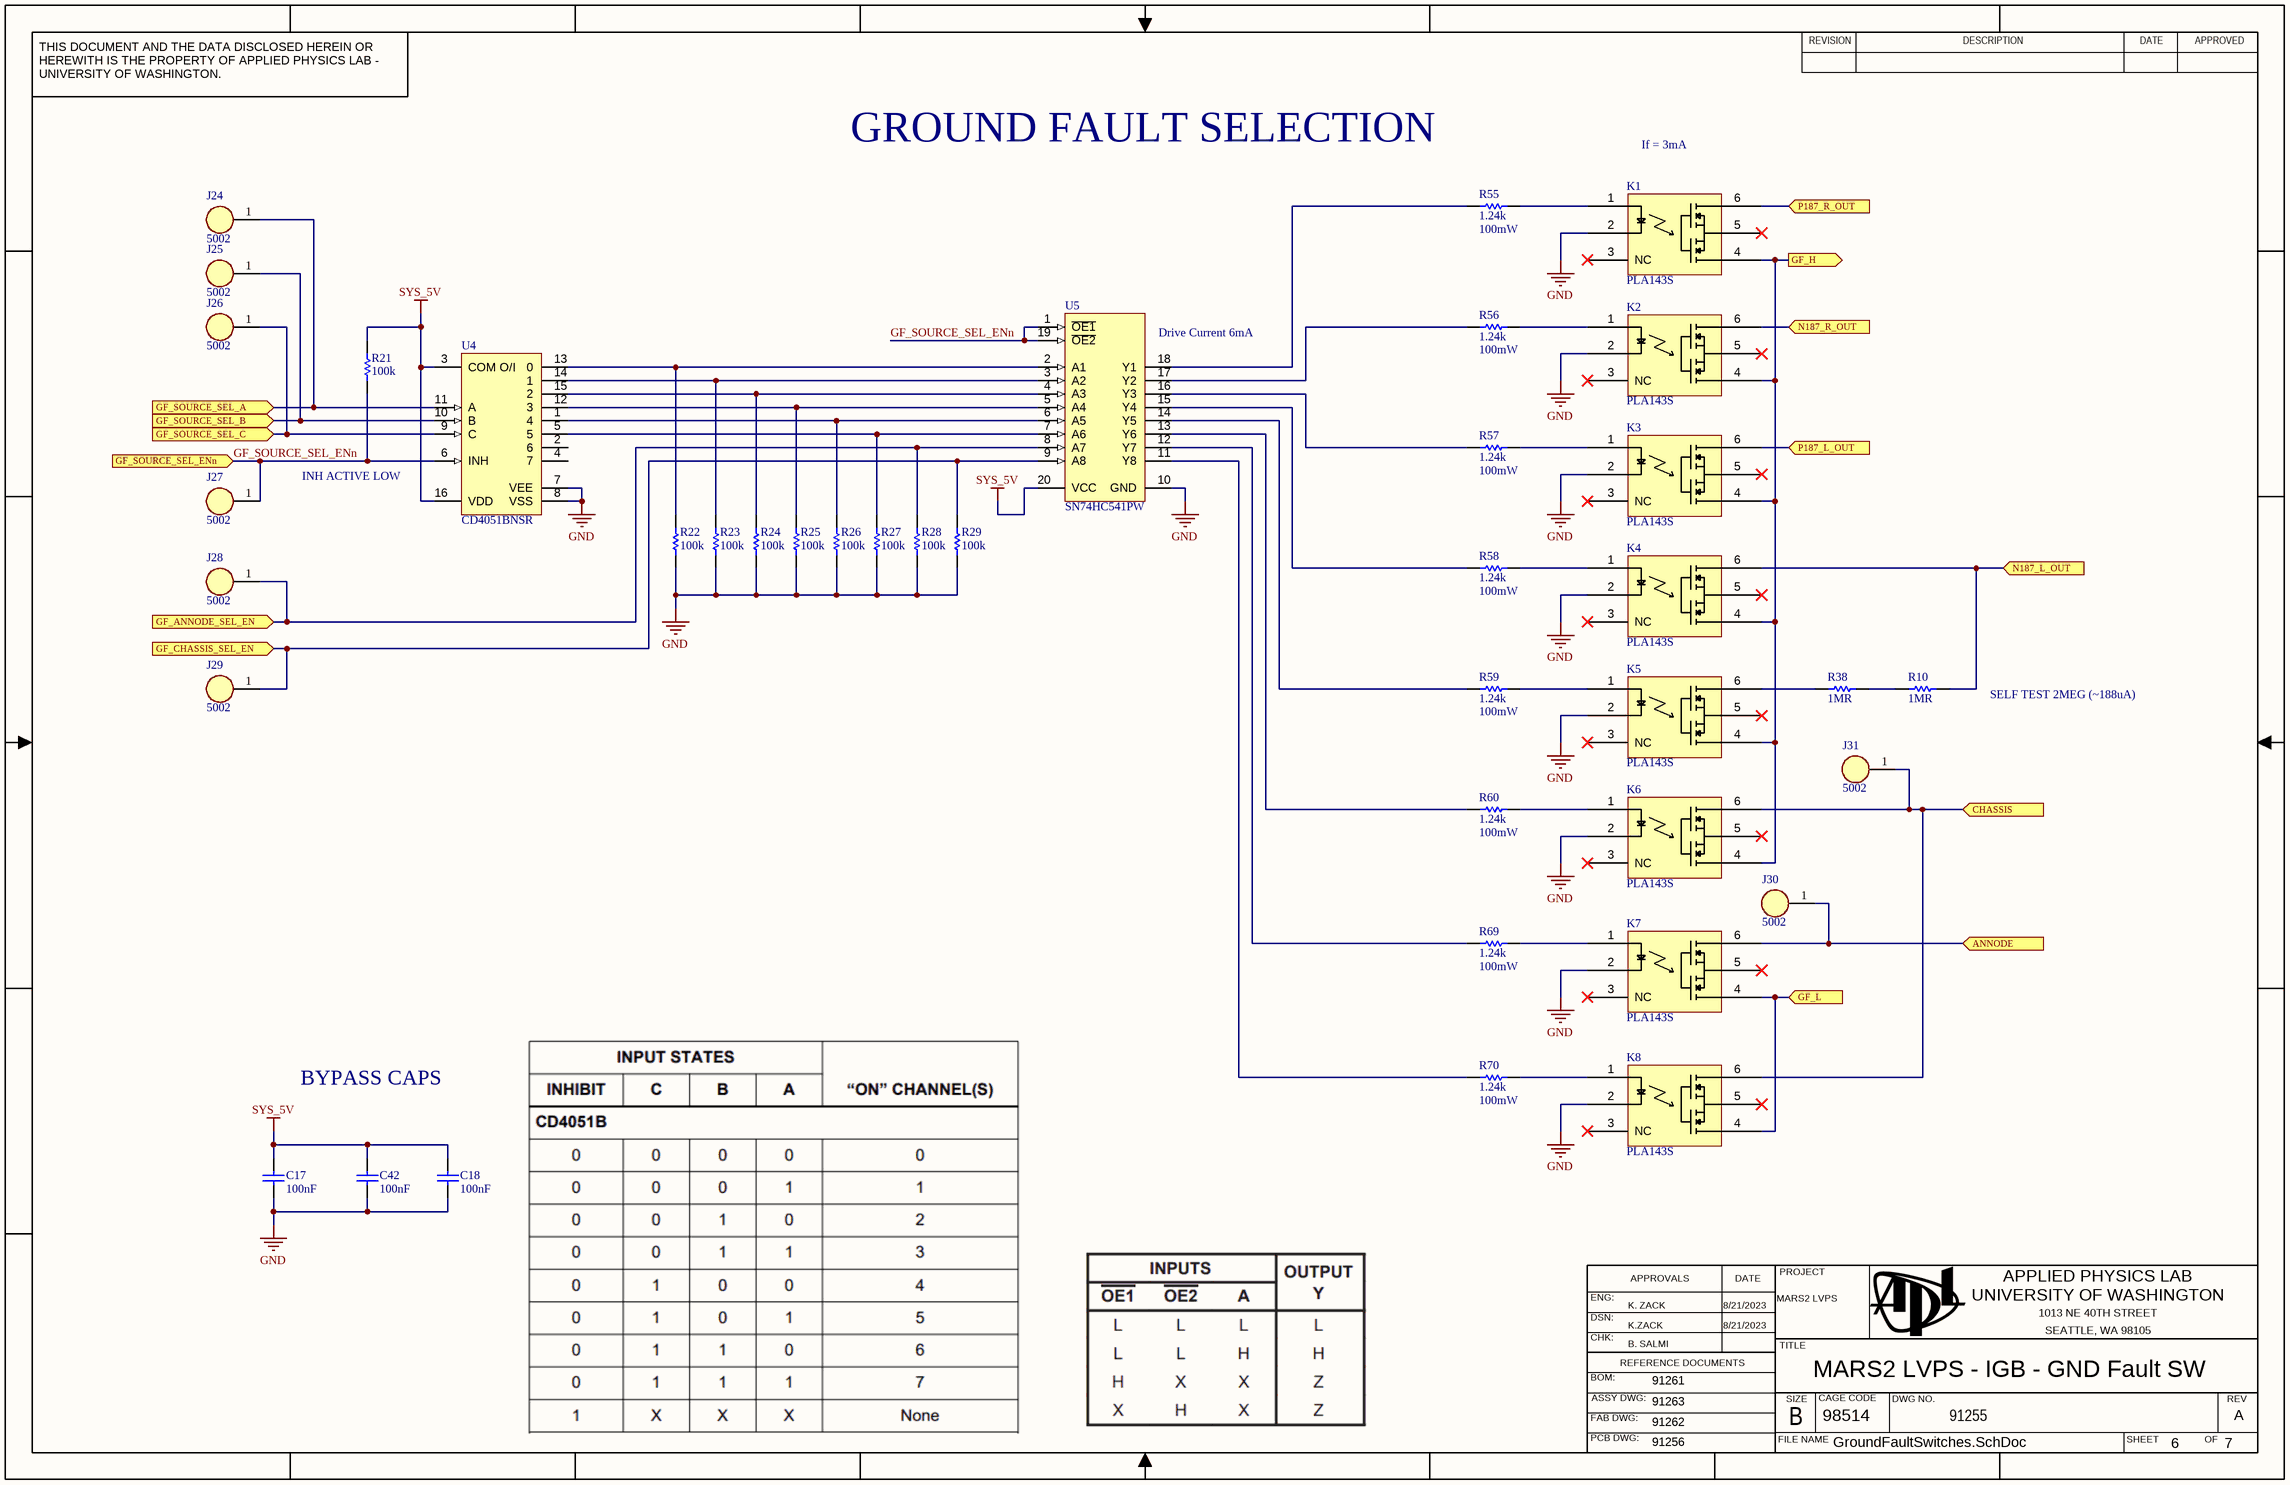
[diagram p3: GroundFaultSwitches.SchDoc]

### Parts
C17  value 100nF  [CAPC1608X90X40NL10T20]  (hidden comment: Capacitor 100 nF +/-10% 50 V 0603)
C18  value 100nF  [CAPC1608X90X40NL10T20]  (hidden comment: Capacitor 100 nF +/-10% 50 V 0603)
C42  value 100nF  [CAPC1608X90X40NL10T20]  (hidden comment: Capacitor 100 nF +/-10% 50 V 0603)
J24  5002  [FP-5002-MFG]
J25  5002  [FP-5002-MFG]
J26  5002  [FP-5002-MFG]
J27  5002  [FP-5002-MFG]
J28  5002  [FP-5002-MFG]
J29  5002  [FP-5002-MFG]
J30  5002  [FP-5002-MFG]
J31  5002  [FP-5002-MFG]
K1  PLA143S  [PLA143S-Footprint-1]
K2  PLA143S  [PLA143S-Footprint-1]
K3  PLA143S  [PLA143S-Footprint-1]
K4  PLA143S  [PLA143S-Footprint-1]
K5  PLA143S  [PLA143S-Footprint-1]
K6  PLA143S  [PLA143S-Footprint-1]
K7  PLA143S  [PLA143S-Footprint-1]
K8  PLA143S  [PLA143S-Footprint-1]
R10  value 1MR  [RESC5025X06M]  (hidden comment: RC2010FK-071ML)
R21  value 100k  [RESC1608X55X25ML10T15]  (hidden comment: Resistor 100k +/-1% 0603 100 mW)
R22  value 100k  [RESC1608X55X25ML10T15]  (hidden comment: Resistor 100k +/-1% 0603 100 mW)
R23  value 100k  [RESC1608X55X25ML10T15]  (hidden comment: Resistor 100k +/-1% 0603 100 mW)
R24  value 100k  [RESC1608X55X25ML10T15]  (hidden comment: Resistor 100k +/-1% 0603 100 mW)
R25  value 100k  [RESC1608X55X25ML10T15]  (hidden comment: Resistor 100k +/-1% 0603 100 mW)
R26  value 100k  [RESC1608X55X25ML10T15]  (hidden comment: Resistor 100k +/-1% 0603 100 mW)
R27  value 100k  [RESC1608X55X25ML10T15]  (hidden comment: Resistor 100k +/-1% 0603 100 mW)
R28  value 100k  [RESC1608X55X25ML10T15]  (hidden comment: Resistor 100k +/-1% 0603 100 mW)
R29  value 100k  [RESC1608X55X25ML10T15]  (hidden comment: Resistor 100k +/-1% 0603 100 mW)
R38  value 1MR  [RESC5025X06M]  (hidden comment: RC2010FK-071ML)
R55  value 1.24k  Power: 100mW  [RESC1609X50X30ML08T20]  (hidden comment: Resistor 1K24 +/-1% 0603 100 mW)
R56  value 1.24k  Power: 100mW  [RESC1609X50X30ML08T20]  (hidden comment: Resistor 1K24 +/-1% 0603 100 mW)
R57  value 1.24k  Power: 100mW  [RESC1609X50X30ML08T20]  (hidden comment: Resistor 1K24 +/-1% 0603 100 mW)
R58  value 1.24k  Power: 100mW  [RESC1609X50X30ML08T20]  (hidden comment: Resistor 1K24 +/-1% 0603 100 mW)
R59  value 1.24k  Power: 100mW  [RESC1609X50X30ML08T20]  (hidden comment: Resistor 1K24 +/-1% 0603 100 mW)
R60  value 1.24k  Power: 100mW  [RESC1609X50X30ML08T20]  (hidden comment: Resistor 1K24 +/-1% 0603 100 mW)
R69  value 1.24k  Power: 100mW  [RESC1609X50X30ML08T20]  (hidden comment: Resistor 1K24 +/-1% 0603 100 mW)
R70  value 1.24k  Power: 100mW  [RESC1609X50X30ML08T20]  (hidden comment: Resistor 1K24 +/-1% 0603 100 mW)
U4  CD4051BNSR  [NS0016A_M]
U5  SN74HC541PW  [PW0020A_L]

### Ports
ANNODE (in), CHASSIS (in), GF_ANNODE_SEL_EN (in), GF_CHASSIS_SEL_EN (in), GF_H (out), GF_L (in), GF_SOURCE_SEL_A (in), GF_SOURCE_SEL_B (in), GF_SOURCE_SEL_C (in), GF_SOURCE_SEL_ENn (in), N187_L_OUT (in), N187_R_OUT (in), P187_L_OUT (in), P187_R_OUT (in)

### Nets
GND: C17.1 C18.1 C42.1 K1.2(-_CNTL) K2.2(-_CNTL) K3.2(-_CNTL) K4.2(-_CNTL) K5.2(-_CNTL) K6.2(-_CNTL) K7.2(-_CNTL) K8.2(-_CNTL) R22.1 R23.1 R24.1 R25.1 R26.1 R27.1 R28.1 R29.1 U4.7(VEE) U4.8(VSS) U5.10(GND)
SYS_5V: C17.2 C18.2 C42.2 R21.1 U4.3(COM_O/I) U4.16(VDD) U5.20(VCC)
GF_SOURCE_SEL_ENn: J27.1 R21.2 U4.6(INH) U5.1(~{OE1}) U5.19(~{OE2}) ; port GF_SOURCE_SEL_ENn
N187_L_OUT: K4.6(DRAIN) R10.2 ; port N187_L_OUT
N187_R_OUT: K2.6(DRAIN) ; port N187_R_OUT
P187_L_OUT: K3.6(DRAIN) ; port P187_L_OUT
P187_R_OUT: K1.6(DRAIN) ; port P187_R_OUT
NetJ3_1: J30.1 K7.6(DRAIN) ; port ANNODE
NetJ3_2: J31.1 K6.6(DRAIN) K8.6(DRAIN) ; port CHASSIS
NetJ9_1: J24.1 U4.11(A) ; port GF_SOURCE_SEL_A
NetJ9_3: J25.1 U4.10(B) ; port GF_SOURCE_SEL_B
NetJ9_5: J26.1 U4.9(C) ; port GF_SOURCE_SEL_C
NetJ9_9: J28.1 R28.2 U5.8(A7) ; port GF_ANNODE_SEL_EN
NetJ9_11: J29.1 R29.2 U5.9(A8) ; port GF_CHASSIS_SEL_EN
NetJ21_1: K1.4(DRAIN) K2.4(DRAIN) K3.4(DRAIN) K4.4(DRAIN) K5.4(DRAIN) K6.4(DRAIN) ; port GF_H
NetJ22_1: K7.4(DRAIN) K8.4(DRAIN) ; port GF_L
NetK1_1: K1.1(+_CNTL) R55.2
NetK2_1: K2.1(+_CNTL) R56.2
NetK3_1: K3.1(+_CNTL) R57.2
NetK4_1: K4.1(+_CNTL) R58.2
NetK5_1: K5.1(+_CNTL) R59.2
NetK5_6: K5.6(DRAIN) R38.1
NetK6_1: K6.1(+_CNTL) R60.2
NetK7_1: K7.1(+_CNTL) R69.2
NetK8_1: K8.1(+_CNTL) R70.2
NetR10_1: R10.1 R38.2
NetR22_2: R22.2 U4.13(0) U5.2(A1)
NetR23_2: R23.2 U4.14(1) U5.3(A2)
NetR24_2: R24.2 U4.15(2) U5.4(A3)
NetR25_2: R25.2 U4.12(3) U5.5(A4)
NetR26_2: R26.2 U4.1(4) U5.6(A5)
NetR27_2: R27.2 U4.5 U5.7(A6)
NetR55_1: R55.1 U5.18(Y1)
NetR56_1: R56.1 U5.17(Y2)
NetR57_1: R57.1 U5.16(Y3)
NetR58_1: R58.1 U5.15(Y4)
NetR59_1: R59.1 U5.14(Y5)
NetR60_1: R60.1 U5.13(Y6)
NetR69_1: R69.1 U5.12(Y7)
NetR70_1: R70.1 U5.11(Y8)

Not connected (* = marked no-connect by the designer): K1 3(NC)* 5(SOURCE)*; K2 3(NC)* 5(SOURCE)*; K3 3(NC)* 5(SOURCE)*; K4 3(NC)* 5(SOURCE)*; K5 3(NC)* 5(SOURCE)*; K6 3(NC)* 5(SOURCE)*; K7 3(NC)* 5(SOURCE)*; K8 3(NC)* 5(SOURCE)*; U4 2(6) 4(7)

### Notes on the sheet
- GROUND FAULT SELECTION
- If = 3mA
- (near U5) Drive Current 6mA
- INH ACTIVE LOW
- SELF TEST 2MEG (
  88uA)
- BYPASS CAPS

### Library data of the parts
C17 C18 C42 = CMP-001-00017-14: as C12 on sheet GroundFaultDetection
J24-J31 = CMP-002-00083-3: as J21 on sheet GroundFaultDetection
K1-K8 = CMP-008-00005-3: Relay SSR 50mA 1.4V DC-IN 0.1A 600V AC/DC-OUT 6-Pin PDIP SMD Tube; Load Current: 100mA; On-State Resistance: 50R; Max Power Dissipation: 800mW; Input Type: DC; Isolation Voltage: 4kV; Throw Configuration: SPST
R10 R38 = CMP-009-01250-3: Res Thick Film 2010 1M Ohm 1% 3/4W ±100ppm/°C Molded SMD SMD Embossed T/R; Decade: 1MEG; Power Rating: 750mW; Voltage Rating: 200V
R21-R29 = CMP-009-00023-6: Chip Resistor, 100 KOhm, +/- 1%, 0.1 W, -55 to 155 degC, 0603 (1608 Metric); Voltage Rating: 50V; Power: 100mW
R55-R60 R69 R70 = CMP-009-00795-4: Chip Resistor, 1.24k Ohm, +/- 1%, 0.1 W, -55 to 155 degC, 0603 (1608 Metric); Voltage Rating: 75V; Decade: 1k
U4 = CMP-016-00011-2: 1 Circuit IC Switch 8:1 240 Ohm 16-SO; Operating Supply Voltage: 18V; Propagation Delay: 60ns; Turn-Off Delay Time: 450ns; Min Supply Voltage: 3V; Number of Inputs: 8; On-State Resistance: 240R; Supply Type: Single,Dual; Operating Supply Current: 80nA; Logic Function: Multiplexer,Demultiplexer; Bandwidth: 20MHz; Number of Channels: 1; Max Supply Voltage: 20V; Polarity: Non-Inverting; Nominal Supply Current: 100uA; Turn-On Delay Time: 720ns; Min Dual Supply Voltage: 2.5V; Max Dual Supply Voltage: 9V
U5 = CMP-016-00012-2: Buffer/Line Driver 8-CH Non-Inverting 3-ST CMOS 20-Pin TSSOP Tube; Max Output Current: 7.8mA; Output Type: 3-STATE; Number of Bits per Element: 8; Turn-On Delay Time: 165ns; Number of Bits: 6; Max Supply Voltage: 6V; Propagation Delay: 28ns; Operating Supply Voltage: 5V; Logic Function: Buffer,Inverting; Number of Elements: 1; High Level Output Current: -7.8mA; Min Supply Voltage: 2V; Quiescent Current: 8uA

## Sheet InputProtection.SchDoc: MARS2 LVPS - IGB - Input Protection
size 431 x 279 mm; Organization: ORGANIZATION; Address1: APPLIED PHYSICS LAB; Address2: UNIVERSITY OF WASHINGTON; Address3: 1013 NE 40TH STREET; Address4: SEATTLE, WA 98105; DocumentNumber: 4; Revision: -; SheetNumber: 4; SheetTotal: 7; ENG_APP_DATE: --/--/--; DSN_APP_DATE: --/--/--; CHK_APP_DATE: --/--/--
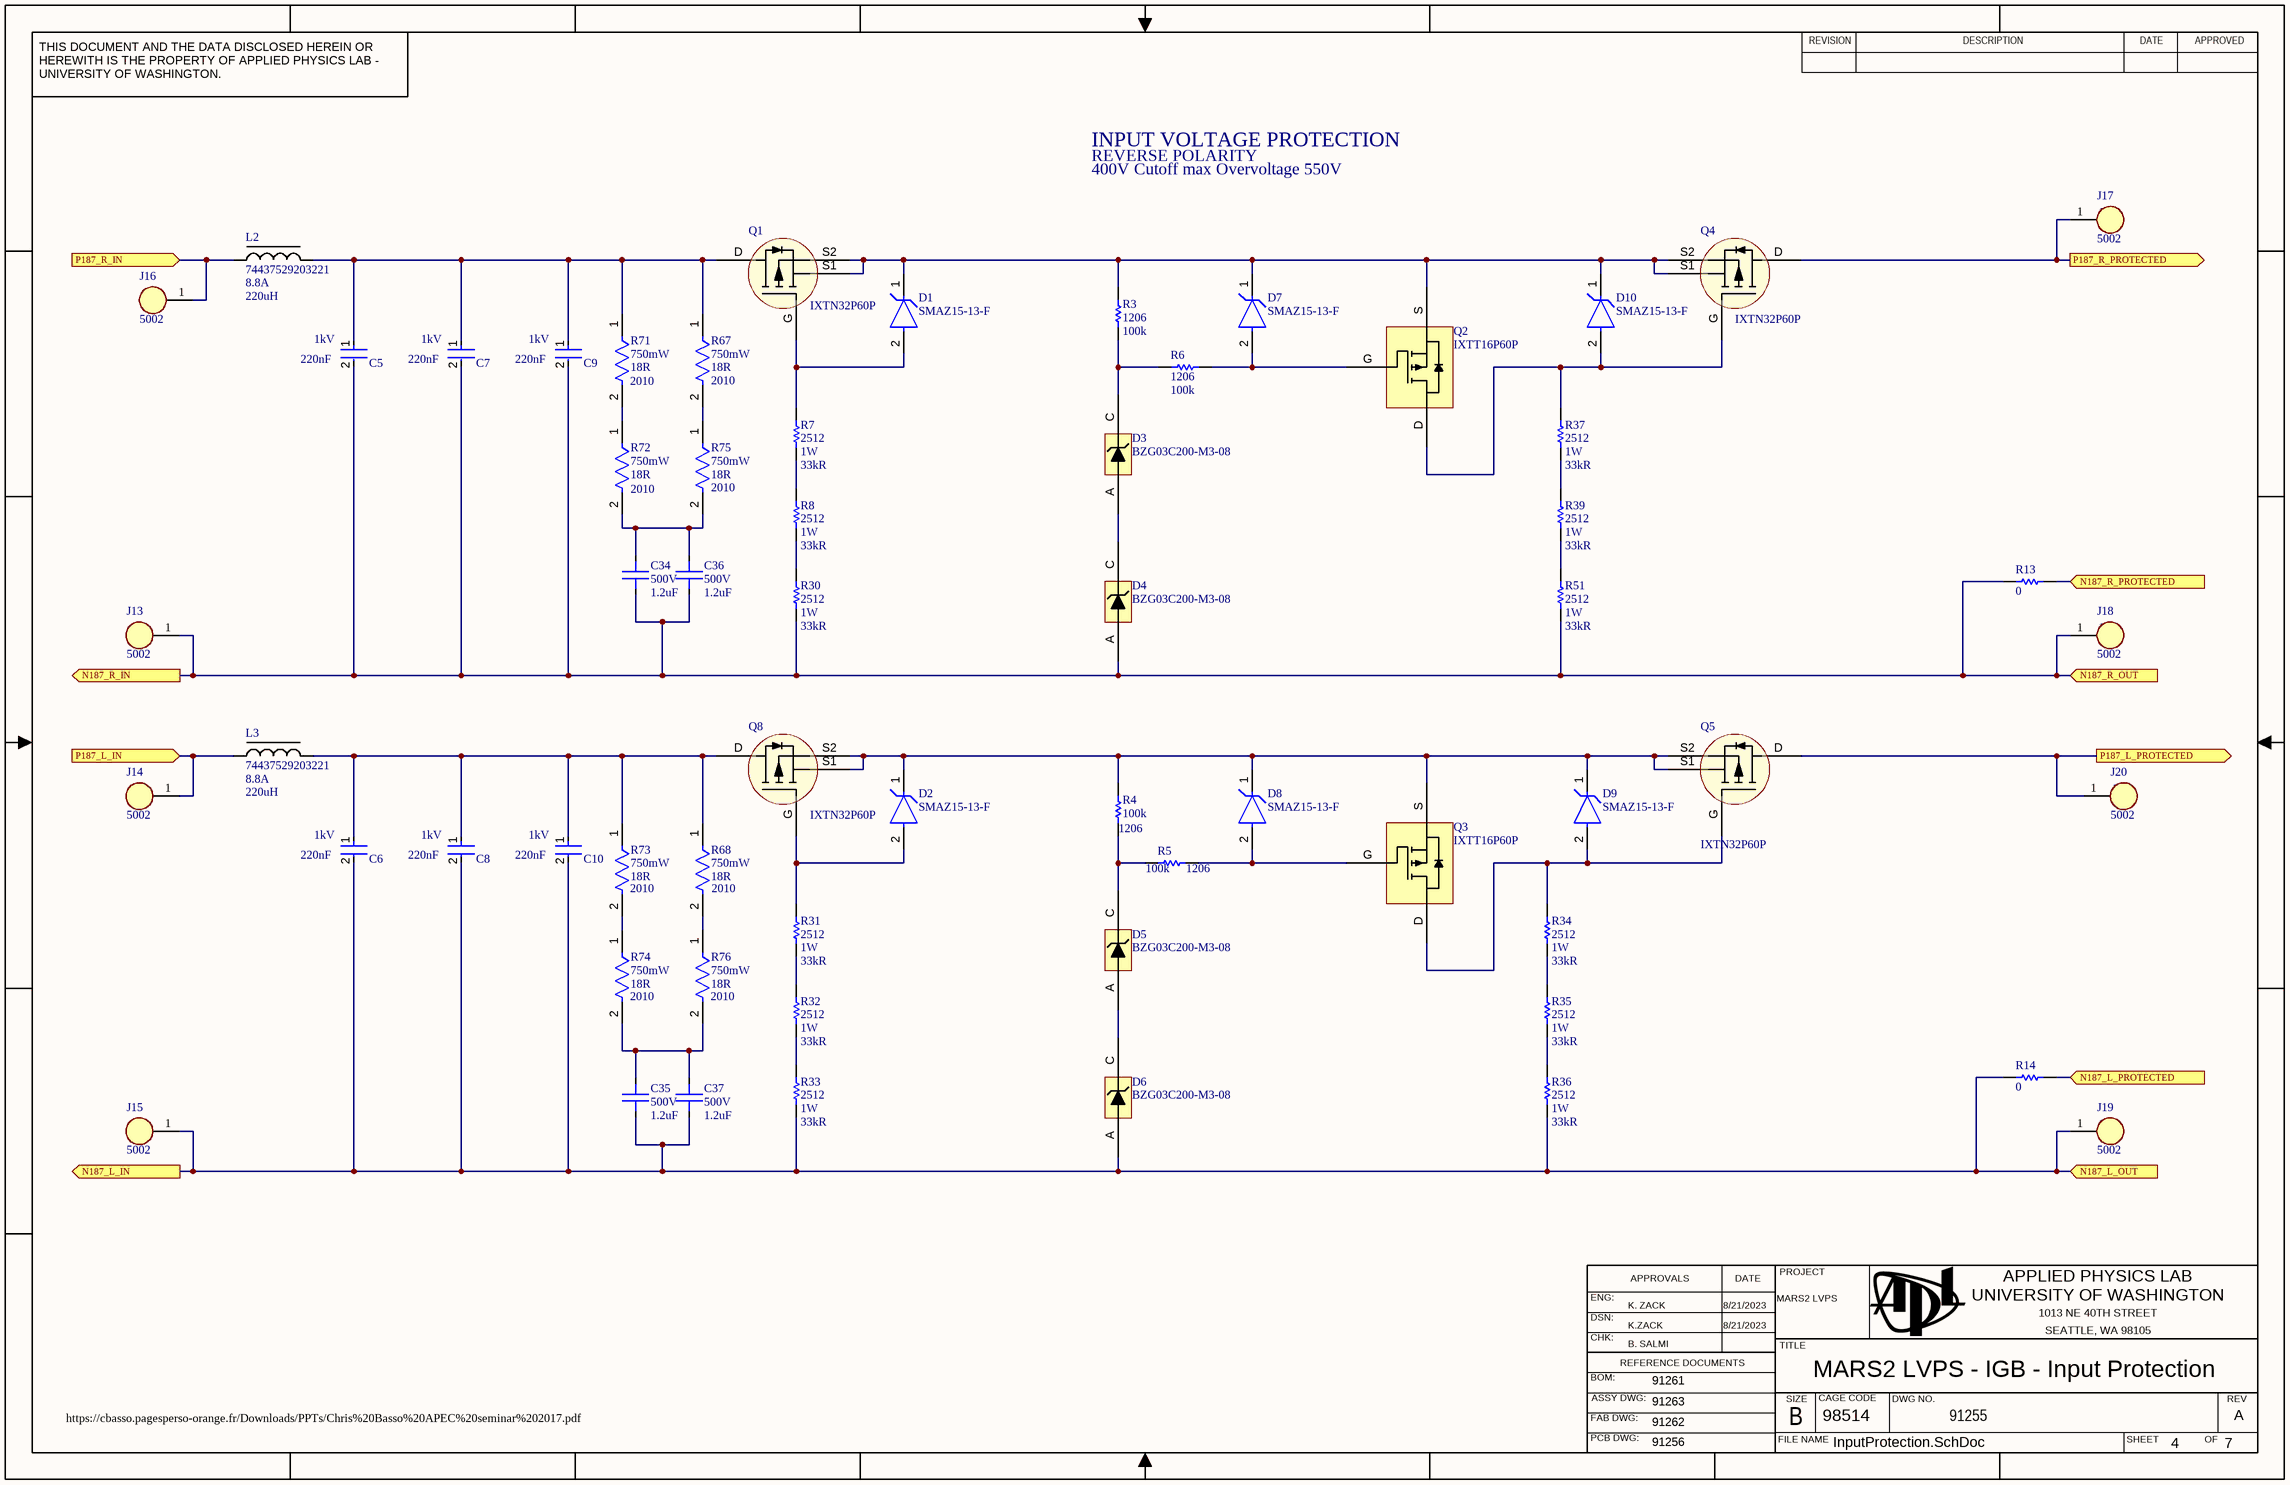
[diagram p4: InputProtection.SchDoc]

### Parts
C5  value 220nF  Voltage: 1kV  [FP-RDEUE1+0_5-MFG]  (hidden comment: Capacitor 0.22uF, 20%, 1kV,X7R,Radial)
C6  value 220nF  Voltage: 1kV  [FP-RDEUE1+0_5-MFG]  (hidden comment: Capacitor 0.22uF, 20%, 1kV,X7R,Radial)
C7  value 220nF  Voltage: 1kV  [FP-RDEUE1+0_5-MFG]  (hidden comment: Capacitor 0.22uF, 20%, 1kV,X7R,Radial)
C8  value 220nF  Voltage: 1kV  [FP-RDEUE1+0_5-MFG]  (hidden comment: Capacitor 0.22uF, 20%, 1kV,X7R,Radial)
C9  value 220nF  Voltage: 1kV  [FP-RDEUE1+0_5-MFG]  (hidden comment: Capacitor 0.22uF, 20%, 1kV,X7R,Radial)
C10  value 220nF  Voltage: 1kV  [FP-RDEUE1+0_5-MFG]  (hidden comment: Capacitor 0.22uF, 20%, 1kV,X7R,Radial)
C34  Voltage Rating: 500V  Capacitance: 1.2uF  [Capacitor 1.2uF 20% 500V X7R-Footprint-1]  (hidden comment: Capacitor 1.2uF 20% 500V X7R)
C35  Voltage Rating: 500V  Capacitance: 1.2uF  [Capacitor 1.2uF 20% 500V X7R-Footprint-1]  (hidden comment: Capacitor 1.2uF 20% 500V X7R)
C36  Voltage Rating: 500V  Capacitance: 1.2uF  [Capacitor 1.2uF 20% 500V X7R-Footprint-1]  (hidden comment: Capacitor 1.2uF 20% 500V X7R)
C37  Voltage Rating: 500V  Capacitance: 1.2uF  [Capacitor 1.2uF 20% 500V X7R-Footprint-1]  (hidden comment: Capacitor 1.2uF 20% 500V X7R)
D1  SMAZ15-13-F  [FP-SMA-MFG]
D2  SMAZ15-13-F  [FP-SMA-MFG]
D3  BZG03C200-M3-08  [BZG03C200-M3-08-Footprint-1]
D4  BZG03C200-M3-08  [BZG03C200-M3-08-Footprint-1]
D5  BZG03C200-M3-08  [BZG03C200-M3-08-Footprint-1]
D6  BZG03C200-M3-08  [BZG03C200-M3-08-Footprint-1]
D7  SMAZ15-13-F  [FP-SMA-MFG]
D8  SMAZ15-13-F  [FP-SMA-MFG]
D9  SMAZ15-13-F  [FP-SMA-MFG]
D10  SMAZ15-13-F  [FP-SMA-MFG]
J13  5002  [FP-5002-MFG]
J14  5002  [FP-5002-MFG]
J15  5002  [FP-5002-MFG]
J16  5002  [FP-5002-MFG]
J17  5002  [FP-5002-MFG]
J18  5002  [FP-5002-MFG]
J19  5002  [FP-5002-MFG]
J20  5002  [FP-5002-MFG]
L2  74437529203221  Current: 8.8A  Inductance: 220uH  [74437529203221-Footprint-1]
L3  74437529203221  Current: 8.8A  Inductance: 220uH  [74437529203221-Footprint-1]
Q1  IXTN32P60P  [IXTN32P60P-Footprint-1]
Q2  IXTT16P60P  [DPAK545P1890X510-3N]
Q3  IXTT16P60P  [DPAK545P1890X510-3N]
Q4  IXTN32P60P  [IXTN32P60P-Footprint-1]
Q5  IXTN32P60P  [IXTN32P60P-Footprint-1]
Q8  IXTN32P60P  [IXTN32P60P-Footprint-1]
R3  value 100k  Case/Package: 1206  [RESC3216X60X45ML15T20]  (hidden comment: Resistor 100k +/-1% 1206 250 mW)
R4  value 100k  Case/Package: 1206  [RESC3216X60X45ML15T20]  (hidden comment: Resistor 100k +/-1% 1206 250 mW)
R5  value 100k  Case/Package: 1206  [RESC3216X60X45ML15T20]  (hidden comment: Resistor 100k +/-1% 1206 250 mW)
R6  value 100k  Case/Package: 1206  [RESC3216X60X45ML15T20]  (hidden comment: Resistor 100k +/-1% 1206 250 mW)
R7  Case Code (Imperial): 2512  Max Power Dissipation: 1W  Resistance: 33kR  [RESC2512(6432)_M]  (hidden comment: Resistor 33K 5% 2512 1W)
R8  Case Code (Imperial): 2512  Max Power Dissipation: 1W  Resistance: 33kR  [RESC2512(6432)_M]  (hidden comment: Resistor 33K 5% 2512 1W)
R13  value 0  [RESC2013X50X35ML15T15]  (hidden comment: Resistor 0R +/- 1% 0805 125 mW)
R14  value 0  [RESC2013X50X35ML15T15]  (hidden comment: Resistor 0R +/- 1% 0805 125 mW)
R30  Case Code (Imperial): 2512  Max Power Dissipation: 1W  Resistance: 33kR  [RESC2512(6432)_M]  (hidden comment: Resistor 33K 5% 2512 1W)
R31  Case Code (Imperial): 2512  Max Power Dissipation: 1W  Resistance: 33kR  [RESC2512(6432)_M]  (hidden comment: Resistor 33K 5% 2512 1W)
R32  Case Code (Imperial): 2512  Max Power Dissipation: 1W  Resistance: 33kR  [RESC2512(6432)_M]  (hidden comment: Resistor 33K 5% 2512 1W)
R33  Case Code (Imperial): 2512  Max Power Dissipation: 1W  Resistance: 33kR  [RESC2512(6432)_M]  (hidden comment: Resistor 33K 5% 2512 1W)
R34  Case Code (Imperial): 2512  Max Power Dissipation: 1W  Resistance: 33kR  [RESC2512(6432)_M]  (hidden comment: Resistor 33K 5% 2512 1W)
R35  Case Code (Imperial): 2512  Max Power Dissipation: 1W  Resistance: 33kR  [RESC2512(6432)_M]  (hidden comment: Resistor 33K 5% 2512 1W)
R36  Case Code (Imperial): 2512  Max Power Dissipation: 1W  Resistance: 33kR  [RESC2512(6432)_M]  (hidden comment: Resistor 33K 5% 2512 1W)
R37  Case Code (Imperial): 2512  Max Power Dissipation: 1W  Resistance: 33kR  [RESC2512(6432)_M]  (hidden comment: Resistor 33K 5% 2512 1W)
R39  Case Code (Imperial): 2512  Max Power Dissipation: 1W  Resistance: 33kR  [RESC2512(6432)_M]  (hidden comment: Resistor 33K 5% 2512 1W)
R51  Case Code (Imperial): 2512  Max Power Dissipation: 1W  Resistance: 33kR  [RESC2512(6432)_M]  (hidden comment: Resistor 33K 5% 2512 1W)
R67  Case Code (Imperial): 2010  Max Power Dissipation: 750mW  Resistance: 18R  [FP-RMCF2010-IPC_A]  (hidden comment: Resistor 18R 5% 2010 750mW)
R68  Case/Package: 2010  Max Power Dissipation: 750mW  Resistance: 18R  [FP-RMCF2010-IPC_A]  (hidden comment: Resistor 18R 5% 2010 750mW)
R71  Case Code (Imperial): 2010  Max Power Dissipation: 750mW  Resistance: 18R  [FP-RMCF2010-IPC_A]  (hidden comment: Resistor 18R 5% 2010 750mW)
R72  Case Code (Imperial): 2010  Max Power Dissipation: 750mW  Resistance: 18R  [FP-RMCF2010-IPC_A]  (hidden comment: Resistor 18R 5% 2010 750mW)
R73  Case/Package: 2010  Max Power Dissipation: 750mW  Resistance: 18R  [FP-RMCF2010-IPC_A]  (hidden comment: Resistor 18R 5% 2010 750mW)
R74  Case/Package: 2010  Max Power Dissipation: 750mW  Resistance: 18R  [FP-RMCF2010-IPC_A]  (hidden comment: Resistor 18R 5% 2010 750mW)
R75  Case Code (Imperial): 2010  Max Power Dissipation: 750mW  Resistance: 18R  [FP-RMCF2010-IPC_A]  (hidden comment: Resistor 18R 5% 2010 750mW)
R76  Case/Package: 2010  Max Power Dissipation: 750mW  Resistance: 18R  [FP-RMCF2010-IPC_A]  (hidden comment: Resistor 18R 5% 2010 750mW)

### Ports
N187_L_IN (out), N187_L_OUT (in), N187_L_PROTECTED (in), N187_R_IN (out), N187_R_OUT (in), N187_R_PROTECTED (in), P187_L_IN (in), P187_L_PROTECTED (out), P187_R_IN (in), P187_R_PROTECTED (out)

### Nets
L_INPUT_COMMON: R14.2 ; port N187_L_PROTECTED
N187_L_OUT: C6.2 C8.2 C10.2 C35.1 C37.1 D6.A J15.1 J19.1 R14.1 R33.1 R36.1 ; port N187_L_IN, port N187_L_OUT
N187_R_OUT: C5.2 C7.2 C9.2 C34.1 C36.1 D4.A J13.1 J18.1 R13.1 R30.1 R51.1 ; port N187_R_IN, port N187_R_OUT
R_INPUT_COMMON: R13.2 ; port N187_R_PROTECTED
NetC5_1: C5.1 C7.1 C9.1 L2.2 Q1.D R67.1 R71.1
NetC6_1: C6.1 C8.1 C10.1 L3.2 Q8.D R68.1 R73.1
NetC34_2: C34.2 C36.2 R72.2 R75.2
NetC35_2: C35.2 C37.2 R74.2 R76.2
NetD1_1: D1.1(C) D7.1(C) D10.1(C) Q1.S1 Q1.S2 Q2.S Q4.S1 Q4.S2 R3.2
NetD1_2: D1.2(A) Q1.G R7.2
NetD2_1: D2.1(C) D8.1(C) D9.1(C) Q3.S Q5.S1 Q5.S2 Q8.S1 Q8.S2 R4.2
NetD2_2: D2.2(A) Q8.G R31.2
NetD3_A: D3.A D4.C
NetD3_C: D3.C R3.1 R6.1
NetD5_A: D5.A D6.C
NetD5_C: D5.C R4.1 R5.1
NetD7_2: D7.2(A) Q2.G R6.2
NetD8_2: D8.2(A) Q3.G R5.2
NetD9_2: D9.2(A) Q3.D Q5.G R34.2
NetD10_2: D10.2(A) Q2.D Q4.G R37.2
NetJ1_A: J16.1 L2.1 ; port P187_R_IN
NetJ2_A: J14.1 L3.1 ; port P187_L_IN
NetJ17_1: J17.1 Q4.D ; port P187_R_PROTECTED
NetJ20_1: J20.1 Q5.D ; port P187_L_PROTECTED
NetR7_1: R7.1 R8.2
NetR8_1: R8.1 R30.2
NetR31_1: R31.1 R32.2
NetR32_1: R32.1 R33.2
NetR34_1: R34.1 R35.2
NetR35_1: R35.1 R36.2
NetR37_1: R37.1 R39.2
NetR39_1: R39.1 R51.2
NetR67_2: R67.2 R75.1
NetR68_2: R68.2 R76.1
NetR71_2: R71.2 R72.1
NetR73_2: R73.2 R74.1

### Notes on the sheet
- INPUT VOLTAGE PROTECTION
- REVERSE POLARITY
- 400V Cutoff max Overvoltage 550V
- https://cbasso.pagesperso-orange.fr/Downloads/PPTs/Chris%20Basso%20APEC%20seminar%202017.pdf

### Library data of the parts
C5-C10 = CMP-001-00084-11: Cap Ceramic 0.22uF 1000V X7R 20% Radial 5mm 125°C Bulk; Manufacturer PN: RDER73A224MUB1H03B; Lead Diameter: 0.5mm; Lead/Base Style: Straight; Decade: 100nF
C34-C37 = CMP-001-00207-8: Dipped Radial Lead Multilayer Ceramic Capacitors; Manufacturing PN: KTD501B125M76A0T00; Decade: 1uF
D1 D2 D7-D10 = CMP-004-00031-4: Vz=15V 14.25V~15.75V Izt=50mA P=1W; Max Power Dissipation: 1W; Max Reverse Current: 1uA; Tolerance: 5%; Test Current: 50mA; Impedance: 10; Forward Voltage: 1.2V; Zener Voltage: 15; Element Configuration: Single
D3-D6 = CMP-004-00032-3: Zener Diode Single 200V 6% 500Ohm 3000mW 2-Pin SMA T/R; Current - Reverse Leakage @ Vr: 1 µA @ 150 V; Impedance (Max) (Zzt): 500 Ohms; Power - Max: 1.25W; Voltage - Forward (Vf) (Max) @ If: 1.2 V @ 500 mA
J13-J20 = CMP-002-00083-3: as J21 on sheet GroundFaultDetection
L2 L3 = CMP-006-00021-5: Fixed Ind 220UH 8.8A 36.45 Mohm; Test Frequency: 100kHz; Saturation Current: 5.3A; Self Resonant Frequency: 2.8MHz; DC Resistance (DCR): 36.45mR; Tolerance: 20%; Core Material: Ferrite; Shielding: Shielded
Q1 Q4 Q5 Q8 = CMP-013-00041-4: Mosfet P-ch 600V 32A SOT227B; Voltage: 600; Max Power Dissipation: 890W; Rise Time: 27ns; Polarity: P-CHANNEL; Rds On Max: 350mR; Turn-Off Delay Time: 95ns; Fall Time: 33ns; Input Capacitance: 11.1nF; Transistor Type: PMOS
Q2 Q3 = CMP-013-00034-5: Single P-Channel 600 V 720 mOhm 460 W Power Mosfet - TO-268; Vdss: -600V; Power: 460W; Current: -16A; Drain to Source Voltage (Vdss): 600V; Drain-source On Resistance-Max: 720MR; Continuous Drain Current (ID): 16A; Input Capacitance: 5.12nF; Transistor Type: PMOS
R3-R6 = CMP-009-00025-6: Chip Resistor, 100 KOhm, +/- 1%, 0.25 W, -55 to 155 degC, 1206 (3216 Metric); Voltage Rating: 200V; Power: 250mW
R7 R8 R30-R37 R39 R51 = CMP-009-01196-1: Res Thick Film 2512 33K Ohm 5% 1W ±200ppm/°C Molded SMD SMD Blister T/R; Manufacturer PN: CRCW251233K0JNEG; Voltage Rating: 500V
R13 R14 = CMP-009-00001-7: Chip Resistor, 0 Ohm, +/- 1%, 125 mW, -55 to 155 degC, 0805 (2012 Metric); Power: 125mW; Voltage Rating: 150V
R67 R68 R71-R76 = CMP-009-01190-1: Res Thick Film 2010 18 Ohm 5% 3/4W ±100ppm/°C Molded SMD SMD Plastic T/R; Manufacturer PN: RMCF2010JT18R0; Temperature Coefficient: 200ppm/°C

## Sheet Sensors.SchDoc: MARS2 LVPS - IGB - Sensors
size 431 x 279 mm; Organization: ORGANIZATION; Address1: APPLIED PHYSICS LAB; Address2: UNIVERSITY OF WASHINGTON; Address3: 1013 NE 40TH STREET; Address4: SEATTLE, WA 98105; DocumentNumber: 7; Revision: -; SheetNumber: 7; SheetTotal: 7; ENG_APP_DATE: --/--/--; DSN_APP_DATE: --/--/--; CHK_APP_DATE: --/--/--
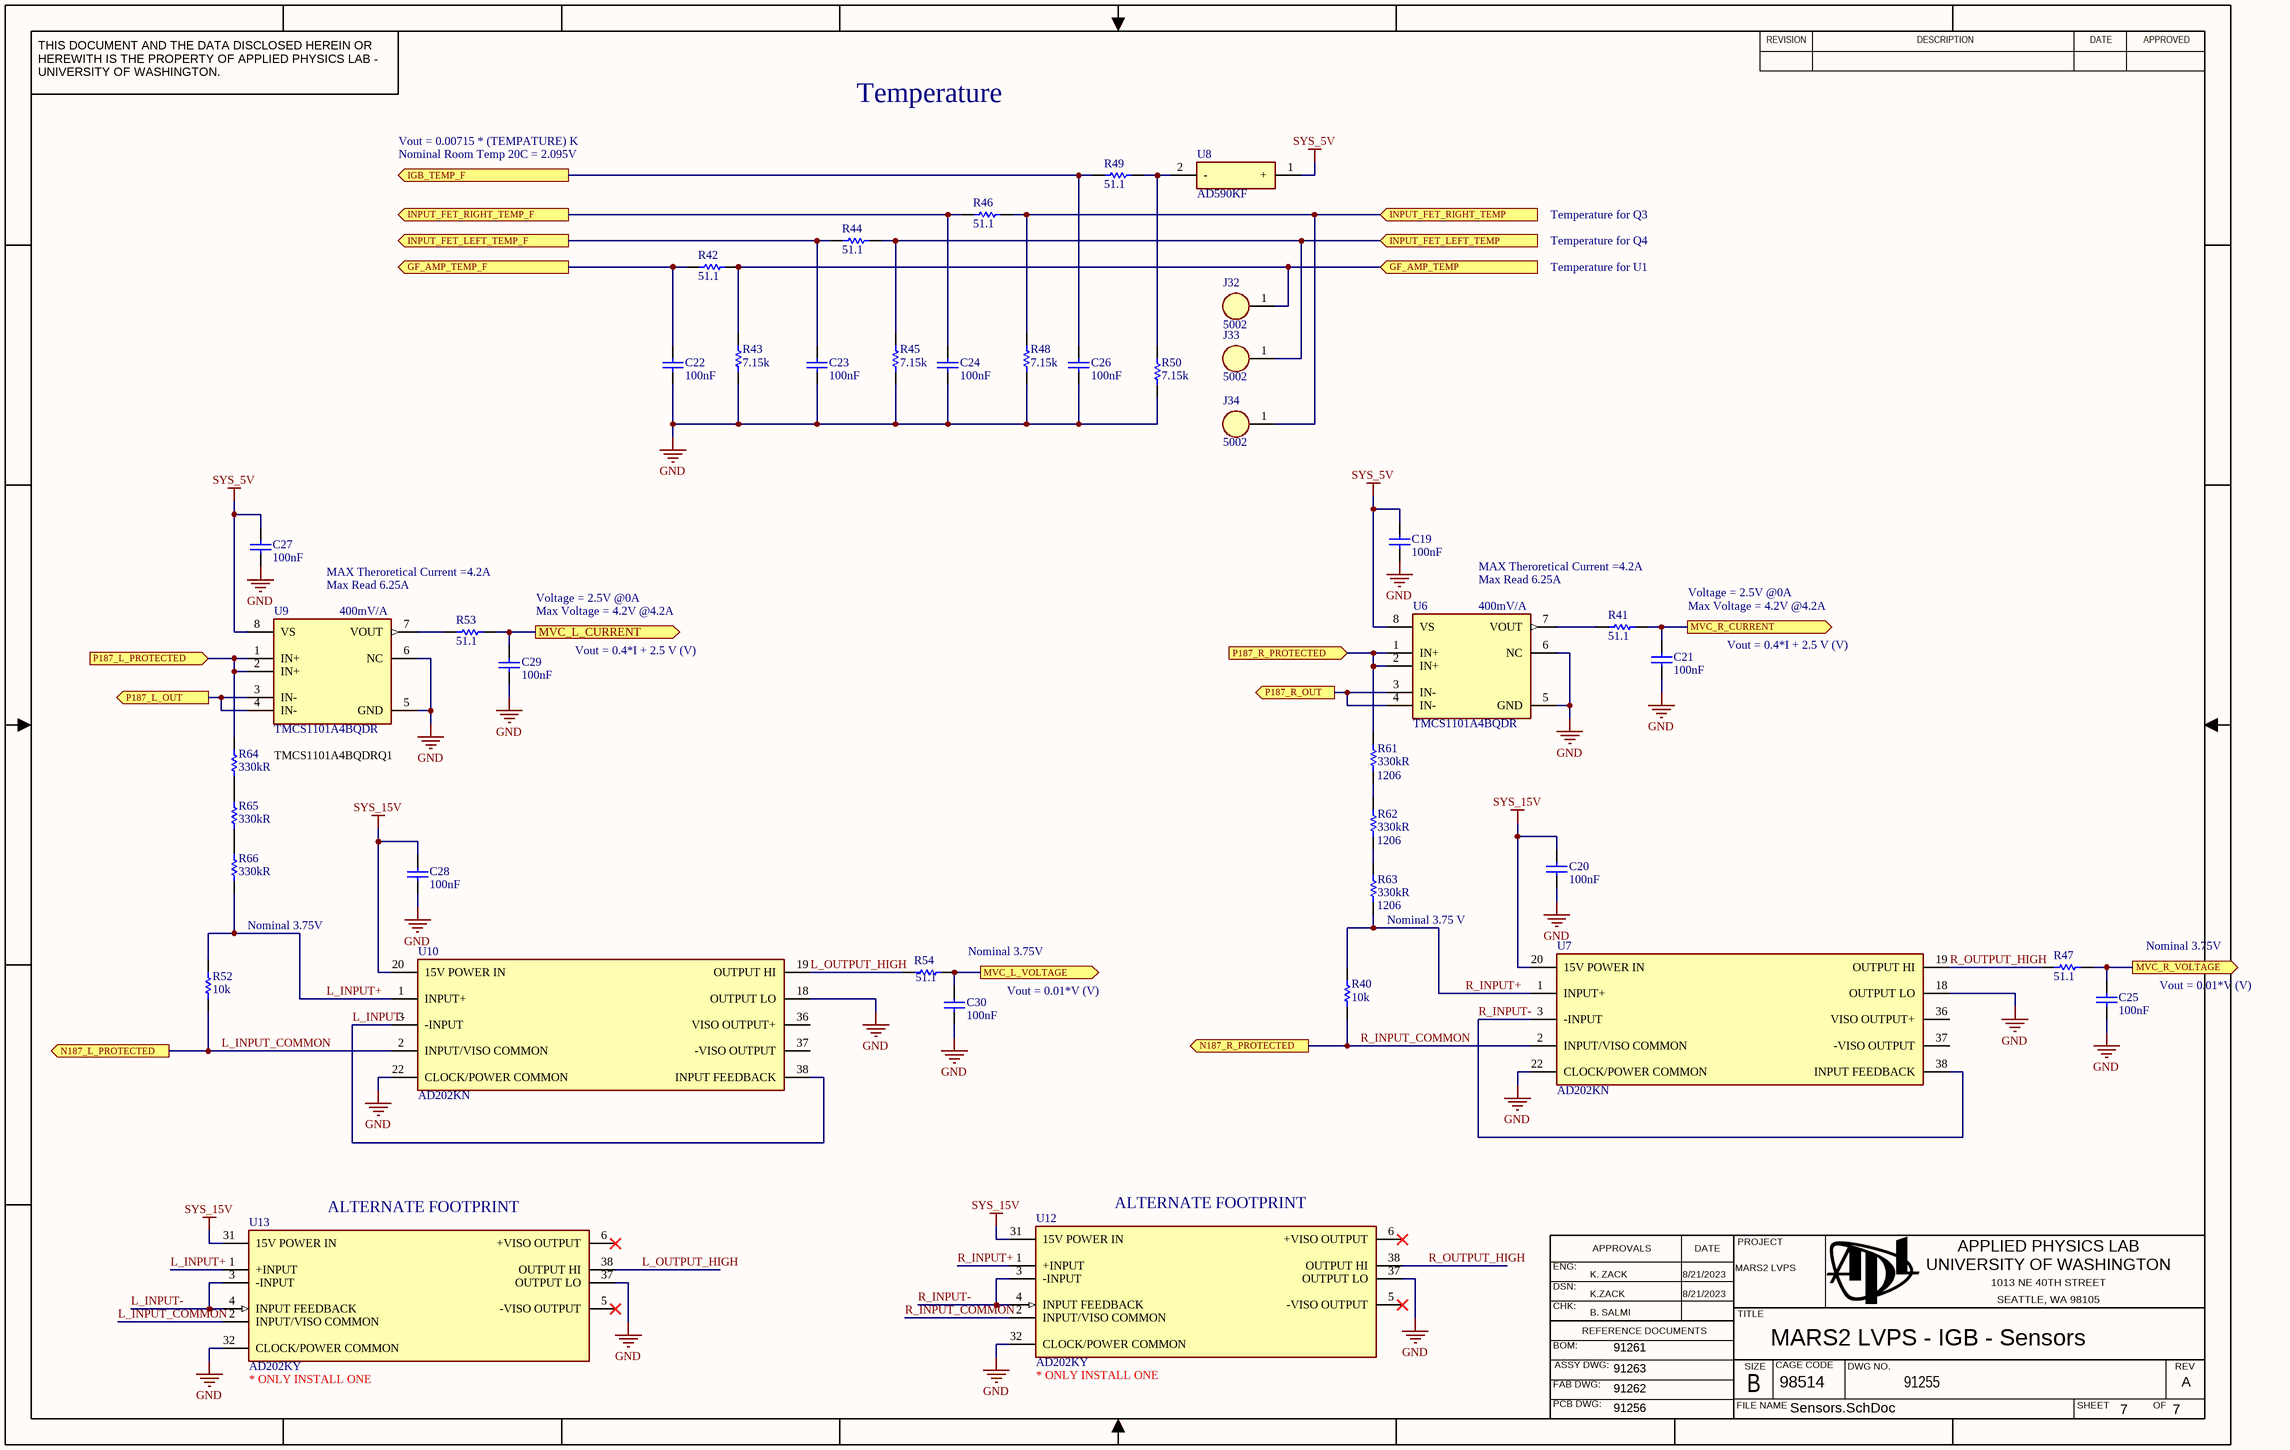
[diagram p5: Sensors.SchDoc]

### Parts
C19  value 100nF  [CAPC1608X90X40NL10T20]  (hidden comment: Capacitor 100 nF +/-10% 50 V 0603)
C20  value 100nF  [CAPC1608X90X40NL10T20]  (hidden comment: Capacitor 100 nF +/-10% 50 V 0603)
C21  value 100nF  [CAPC1608X90X40NL10T20]  (hidden comment: Capacitor 100 nF +/-10% 50 V 0603)
C22  value 100nF  [CAPC1608X90X40NL10T20]  (hidden comment: Capacitor 100 nF +/-10% 50 V 0603)
C23  value 100nF  [CAPC1608X90X40NL10T20]  (hidden comment: Capacitor 100 nF +/-10% 50 V 0603)
C24  value 100nF  [CAPC1608X90X40NL10T20]  (hidden comment: Capacitor 100 nF +/-10% 50 V 0603)
C25  value 100nF  [CAPC1608X90X40NL10T20]  (hidden comment: Capacitor 100 nF +/-10% 50 V 0603)
C26  value 100nF  [CAPC1608X90X40NL10T20]  (hidden comment: Capacitor 100 nF +/-10% 50 V 0603)
C27  value 100nF  [CAPC1608X90X40NL10T20]  (hidden comment: Capacitor 100 nF +/-10% 50 V 0603)
C28  value 100nF  [CAPC1608X90X40NL10T20]  (hidden comment: Capacitor 100 nF +/-10% 50 V 0603)
C29  value 100nF  [CAPC1608X90X40NL10T20]  (hidden comment: Capacitor 100 nF +/-10% 50 V 0603)
C30  value 100nF  [CAPC1608X90X40NL10T20]  (hidden comment: Capacitor 100 nF +/-10% 50 V 0603)
J32  5002  [FP-5002-MFG]
J33  5002  [FP-5002-MFG]
J34  5002  [FP-5002-MFG]
R40  value 10k  [RESC3216X60X45ML15T20]  (hidden comment: Resistor 10k +/-1% 1206 250 mW)
R41  value 51.1  [RESC1609X50X30ML08T20]  (hidden comment: Resistor 51R1 +/-1% 0603 100 mW)
R42  value 51.1  [RESC1609X50X30ML08T20]  (hidden comment: Resistor 51R1 +/-1% 0603 100 mW)
R43  value 7.15k  [RESC1609X50X30ML08T20]  (hidden comment: Resistor 7K15 +/-1% 0603 100 mW)
R44  value 51.1  [RESC1609X50X30ML08T20]  (hidden comment: Resistor 51R1 +/-1% 0603 100 mW)
R45  value 7.15k  [RESC1609X50X30ML08T20]  (hidden comment: Resistor 7K15 +/-1% 0603 100 mW)
R46  value 51.1  [RESC1609X50X30ML08T20]  (hidden comment: Resistor 51R1 +/-1% 0603 100 mW)
R47  value 51.1  [RESC1609X50X30ML08T20]  (hidden comment: Resistor 51R1 +/-1% 0603 100 mW)
R48  value 7.15k  [RESC1609X50X30ML08T20]  (hidden comment: Resistor 7K15 +/-1% 0603 100 mW)
R49  value 51.1  [RESC1609X50X30ML08T20]  (hidden comment: Resistor 51R1 +/-1% 0603 100 mW)
R50  value 7.15k  [RESC1609X50X30ML08T20]  (hidden comment: Resistor 7K15 +/-1% 0603 100 mW)
R52  value 10k  [RESC3216X60X45ML15T20]  (hidden comment: Resistor 10k +/-1% 1206 250 mW)
R53  value 51.1  [RESC1609X50X30ML08T20]  (hidden comment: Resistor 51R1 +/-1% 0603 100 mW)
R54  value 51.1  [RESC1609X50X30ML08T20]  (hidden comment: Resistor 51R1 +/-1% 0603 100 mW)
R61  Case/Package: 1206  Resistance: 330kR  [RESC3216X70X50NL20T25]  (hidden comment: Resistor 330k +/-0.1% 1206 250mW)
R62  Case/Package: 1206  Resistance: 330kR  [RESC3216X70X50NL20T25]  (hidden comment: Resistor 330k +/-0.1% 1206 250mW)
R63  Case/Package: 1206  Resistance: 330kR  [RESC3216X70X50NL20T25]  (hidden comment: Resistor 330k +/-0.1% 1206 250mW)
R64  Resistance: 330kR  [RESC3216X70X50NL20T25]  (hidden comment: Resistor 330k +/-0.1% 1206 250mW)
R65  Resistance: 330kR  [RESC3216X70X50NL20T25]  (hidden comment: Resistor 330k +/-0.1% 1206 250mW)
R66  Resistance: 330kR  [RESC3216X70X50NL20T25]  (hidden comment: Resistor 330k +/-0.1% 1206 250mW)
U6  TMCS1101A4BQDR  [FP-D0008A-IPC_B]
U7  AD202KN  [FP-AD202KN-MFG]
U8  AD590KF  [FP-F-2-MFG]
U9  TMCS1101A4BQDR  [FP-D0008A-IPC_B]
U10  AD202KN  [FP-AD202KN-MFG]
U12  AD202KY  [FP-Y-10-MFG]
U13  AD202KY  [FP-Y-10-MFG]

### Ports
GF_AMP_TEMP (in), GF_AMP_TEMP_F (out), IGB_TEMP_F (out), INPUT_FET_LEFT_TEMP (in), INPUT_FET_LEFT_TEMP_F (out), INPUT_FET_RIGHT_TEMP (in), INPUT_FET_RIGHT_TEMP_F (out), MVC_L_CURRENT (out), MVC_L_VOLTAGE (out), MVC_R_CURRENT (out), MVC_R_VOLTAGE (out), N187_L_PROTECTED (out), N187_R_PROTECTED (out), P187_L_OUT (out), P187_L_PROTECTED (in), P187_R_OUT (out), P187_R_PROTECTED (in)

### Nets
GND: C19.1 C20.1 C21.1 C22.1 C23.1 C24.1 C25.1 C26.1 C27.1 C28.1 C29.1 C30.1 R43.1 R45.1 R48.1 R50.1 U6.5(GND) U6.6(NC) U7.18(OUTPUT_LO) U7.22(CLOCK/POWER_COMMON) U9.5(GND) U9.6(NC) U10.18(OUTPUT_LO) U10.22(CLOCK/POWER_COMMON) U12.32(CLOCK/POWER_COMMON) U12.37(OUTPUT_LO) U13.32(CLOCK/POWER_COMMON) U13.37(OUTPUT_LO)
SYS_5V: C19.2 C27.2 U6.8(VS) U8.1(+) U9.8(VS)
SYS_15V: C20.2 C28.2 U7.20(15V_POWER_IN) U10.20(15V_POWER_IN) U12.31(15V_POWER_IN) U13.31(15V_POWER_IN)
L_INPUT+: R52.2 R66.2 U10.1(INPUT+) U13.1(+INPUT)
L_INPUT-: U10.3(-INPUT) U10.38(INPUT_FEEDBACK) U13.3(-INPUT) U13.4(INPUT_FEEDBACK)
L_INPUT_COMMON: R52.1 U10.2(INPUT/VISO_COMMON) U13.2(INPUT/VISO_COMMON) ; port N187_L_PROTECTED
L_OUTPUT_HIGH: R54.1 U10.19(OUTPUT_HI) U13.38(OUTPUT_HI)
P187_L_OUT: U9.3(IN-) U9.4(IN-) ; port P187_L_OUT
P187_R_OUT: U6.3(IN-) U6.4(IN-) ; port P187_R_OUT
R_INPUT+: R40.2 R63.2 U7.1(INPUT+) U12.1(+INPUT)
R_INPUT-: U7.3(-INPUT) U7.38(INPUT_FEEDBACK) U12.3(-INPUT) U12.4(INPUT_FEEDBACK)
R_INPUT_COMMON: R40.1 U7.2(INPUT/VISO_COMMON) U12.2(INPUT/VISO_COMMON) ; port N187_R_PROTECTED
R_OUTPUT_HIGH: R47.1 U7.19(OUTPUT_HI) U12.38(OUTPUT_HI)
NetC21_2: C21.2 R41.2 ; port MVC_R_CURRENT
NetC22_2: C22.2 R42.1 ; port GF_AMP_TEMP_F
NetC23_2: C23.2 R44.1 ; port INPUT_FET_LEFT_TEMP_F
NetC24_2: C24.2 R46.1 ; port INPUT_FET_RIGHT_TEMP_F
NetC25_2: C25.2 R47.2 ; port MVC_R_VOLTAGE
NetC26_2: C26.2 R49.1 ; port IGB_TEMP_F
NetC29_2: C29.2 R53.2 ; port MVC_L_CURRENT
NetC30_2: C30.2 R54.2 ; port MVC_L_VOLTAGE
NetJ10_1: J32.1 R42.2 R43.2 ; port GF_AMP_TEMP
NetJ10_2: J34.1 R46.2 R48.2 ; port INPUT_FET_RIGHT_TEMP
NetJ10_3: J33.1 R44.2 R45.2 ; port INPUT_FET_LEFT_TEMP
NetJ17_1: R61.1 U6.1(IN+) U6.2(IN+) ; port P187_R_PROTECTED
NetJ20_1: R64.1 U9.1(IN+) U9.2(IN+) ; port P187_L_PROTECTED
NetR41_1: R41.1 U6.7(VOUT)
NetR49_2: R49.2 R50.2 U8.2(-)
NetR53_1: R53.1 U9.7(VOUT)
NetR61_2: R61.2 R62.1
NetR62_2: R62.2 R63.1
NetR64_2: R64.2 R65.1
NetR65_2: R65.2 R66.1

Not connected (* = marked no-connect by the designer): U7 36(VISO_OUTPUT+) 37(-VISO_OUTPUT); U10 36(VISO_OUTPUT+) 37(-VISO_OUTPUT); U12 5(-VISO_OUTPUT)* 6(+VISO_OUTPUT)*; U13 5(-VISO_OUTPUT)* 6(+VISO_OUTPUT)*

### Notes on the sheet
- Vout = 0.00715 * (TEMPATURE) K
- Nominal Room Temp 20C = 2.095V
- Temperature
- Temperature for Q3
- Temperature for U1
- Temperature for Q4
- MAX Theroretical Current =4.2A
- Max Read 6.25A
- (near U9) 400mV/A
- Max Voltage = 4.2V @4.2A
- Voltage = 2.5V @0A
- (near U6) 400mV/A
- Vout = 0.4*I + 2.5 V (V)
- TMCS1101A4BQDRQ1
- Nominal 3.75V
- (near R63) Nominal 3.75 V
- Vout = 0.01*V (V)
- (near U12) ALTERNATE FOOTPRINT
- (near U13) ALTERNATE FOOTPRINT
- (near U13) * ONLY INSTALL ONE
- (near U12) * ONLY INSTALL ONE

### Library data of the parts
C19-C30 = CMP-001-00017-14: as C12 on sheet GroundFaultDetection
J32-J34 = CMP-002-00083-3: as J21 on sheet GroundFaultDetection
R40 R52 = CMP-009-00016-6: Chip Resistor, 10 KOhm, +/- 1%, 0.25 W, -55 to 155 degC, 1206 (3216 Metric); Power: 250mW; Voltage Rating: 200V
R41 R42 R44 R46 R47 R49 R53 R54 = CMP-009-01135-1: Chip Resistor, 51.1 Ohm, +/- 1%, 0.1 W, -55 to 155 degC, 0603 (1608 Metric); Voltage Rating: 75V; Power: 100mW; Decade: 10
R43 R45 R48 R50 = CMP-009-00865-4: Chip Resistor, 7.15k Ohm, +/- 1%, 0.1 W, -55 to 155 degC, 0603 (1608 Metric); Voltage Rating: 75V; Power: 100mW; Decade: 1k
R61-R66 = CMP-009-01192-1: Res Thin Film 1206 330K Ohm 0.1% 1/4W ±25ppm/°C Molded SMD SMD Punched Carrier T/R; Manufacture PN: ERA8AEB334V; Voltage Rating: 300V
U6 U9 = CMP-010-00025-5: Precision isolated bidirectional current sensor with Vsupply ratiometric reference 8-SOIC -40 to 125; Alt PN: TMCS1101A4BQDRQ1; Accuracy: 0.5%; Max Supply Current: 6mA; Sensing Method: Hall Effect; Current Sensing: 5.6A; Linearity: 0.05%; Frequency: 80kHz; Sensitivity: 400mV/A; Number of Channels: 1; Response Time: 6.5us
U7 U10 = CMP-014-00004-2: as U1 on sheet GroundFaultDetection
U8 = CMP-010-00024-2: SENSOR ANALOG -55C-150C 2FLATPK / Two-Twrminal IC Temperature Transducer; Max Supply Voltage: 30V; Min Supply Voltage: 4V; Forward Voltage: 44V; Output Current: 298.2uA
U12 U13 = CMP-014-00002-1: as U11 on sheet GroundFaultDetection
